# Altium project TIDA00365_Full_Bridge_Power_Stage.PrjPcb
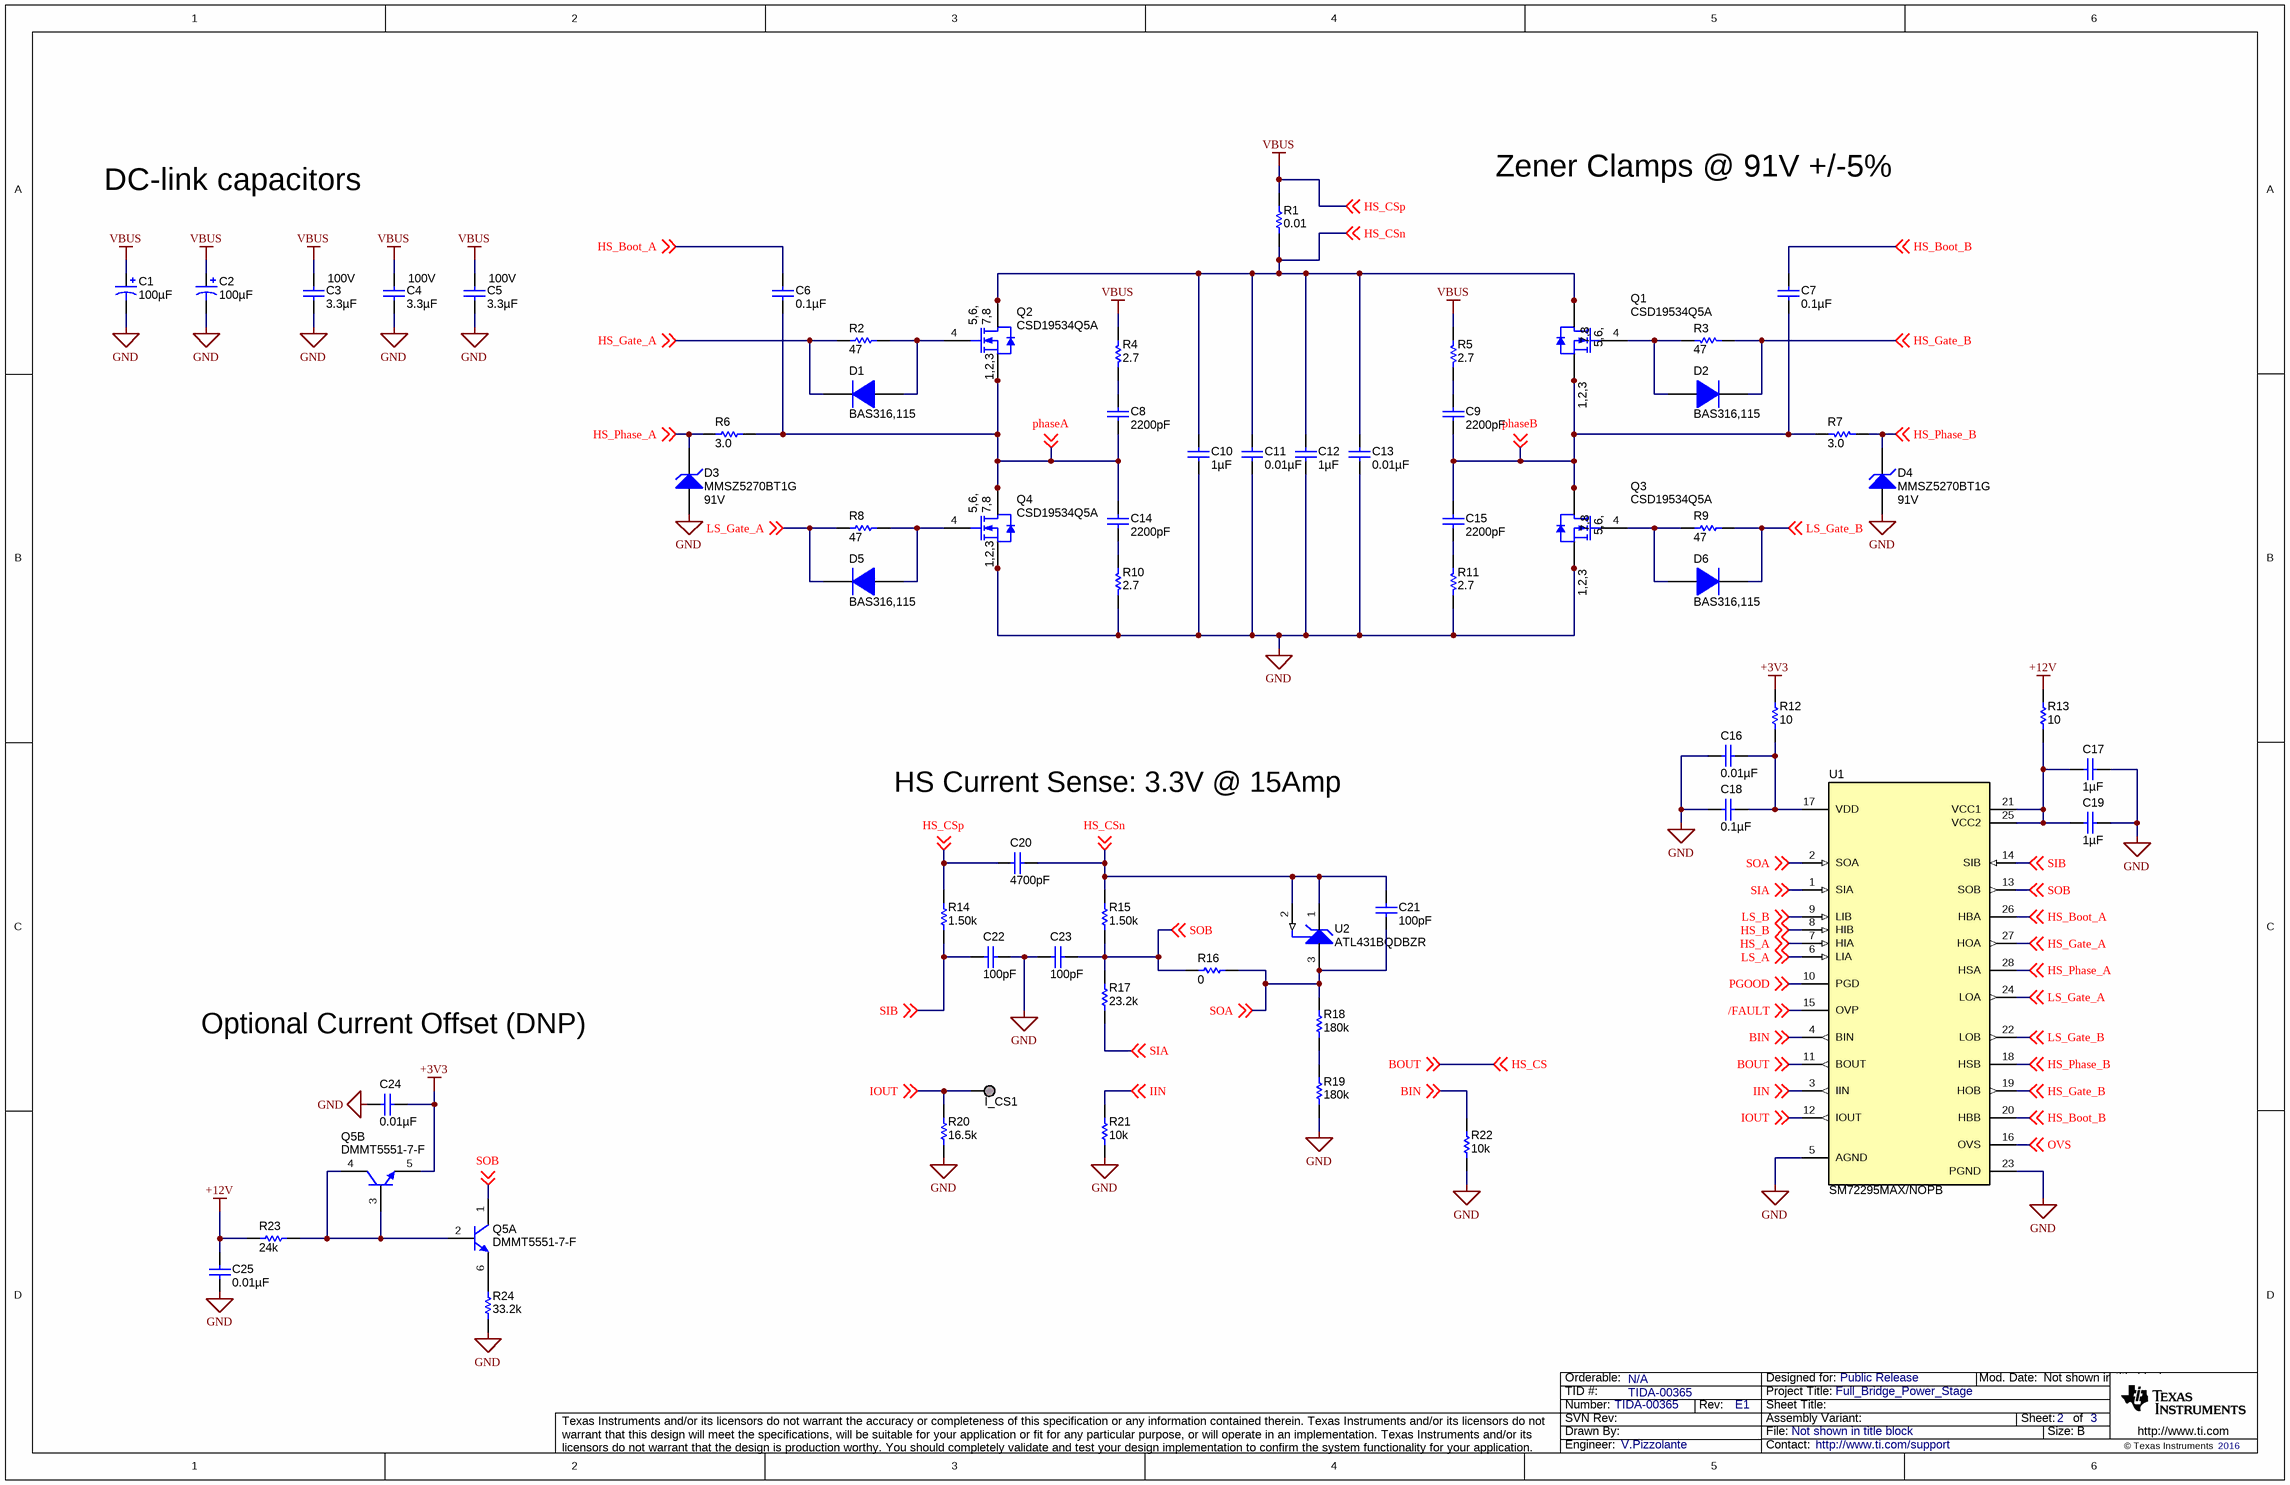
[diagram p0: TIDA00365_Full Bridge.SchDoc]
CopyrightYear: 2016; EVM_Orderable: N/A; PCB_Layout: V.Pizzolante; PCB_Rev: E1; PRJ_Customer: Public Release; PRJ_Engineer: V.Pizzolante; PRJ_Number: TIDA-00365; PRJ_Title: Full_Bridge_Power_Stage; SCH_Rev: E1; TechSupport: http://www.ti.com/support; TID: TIDA-00365
6 sheets, 180 parts. Net scope: global (net labels, ports and power ports of the same name join across sheets).
Board file: TIDA00365.PcbDoc
Sheets:
  TIDA00365_CoverSheet.SchDoc
  TIDA00365_Full Bridge.SchDoc
  TIDA00365_Interfaces.SchDoc
  TIDA00365_Power Supply.SchDoc
  TIDA00365_Protections.SchDoc
  TIDA00365_Hardware.SchDoc

## Sheet TIDA00365_CoverSheet.SchDoc
size 431 x 279 mm; Date: Not shown in title block; ApprovedBy: Not shown in title block; CheckedBy: Not shown in title block; Author: Not shown in title block; CompanyName: Not shown in title block; Engineer: Not shown in title block; Organization: Not shown in title block; Address1: Not shown in title block; Address2: Not shown in title block; Address3: Not shown in title block; Address4: Not shown in title block; DocumentNumber: 1; Revision: Use project parameter SCH_Rev; SheetNumber: 1; SheetTotal: 3

## Sheet TIDA00365_Full Bridge.SchDoc
size 431 x 279 mm; Date: Not shown in title block; ApprovedBy: Not shown in title block; CheckedBy: Not shown in title block; Author: Not shown in title block; CompanyName: Not shown in title block; Engineer: Not shown in title block; Organization: Not shown in title block; Address1: Not shown in title block; Address2: Not shown in title block; Address3: Not shown in title block; Address4: Not shown in title block; DocumentNumber: 1; Revision: Use project parameter SCH_Rev; SheetNumber: 2; SheetTotal: 3

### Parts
C1  ValueDisplayed: 100µF  [WCAP-ATUL_1000x2500]  (hidden comment: 860040875005)
C2  ValueDisplayed: 100µF  [WCAP-ATUL_1000x2500]  (hidden comment: 860040875005)
C3  ValueDisplayed: 3.3µF  Value2: 100V  [1206_190]  (hidden comment: C3216X7S2A335M160AB)
C4  ValueDisplayed: 3.3µF  Value2: 100V  [1206_190]  (hidden comment: C3216X7S2A335M160AB)
C5  ValueDisplayed: 3.3µF  Value2: 100V  [1206_190]  (hidden comment: C3216X7S2A335M160AB)
C6  ValueDisplayed: 0.1µF  [0805_HV]  (hidden comment: C2012X7R2A104K125AA)
C7  ValueDisplayed: 0.1µF  [0805_HV]  (hidden comment: C2012X7R2A104K125AA)
C8  ValueDisplayed: 2200pF  [0603]  (hidden comment: 06031C222JAT2A)
C9  ValueDisplayed: 2200pF  [0603]  (hidden comment: 06031C222JAT2A)
C10  ValueDisplayed: 1µF  [0805_HV]  (hidden comment: C2012X7S2A105K125AB)
C11  ValueDisplayed: 0.01µF  [0603]  (hidden comment: 06031C103KAT2A)
C12  ValueDisplayed: 1µF  [0805_HV]  (hidden comment: C2012X7S2A105K125AB)
C13  ValueDisplayed: 0.01µF  [0603]  (hidden comment: 06031C103KAT2A)
C14  ValueDisplayed: 2200pF  [0603]  (hidden comment: 06031C222JAT2A)
C15  ValueDisplayed: 2200pF  [0603]  (hidden comment: 06031C222JAT2A)
C16  ValueDisplayed: 0.01µF  [0402]  (hidden comment: 885012205031)
C17  ValueDisplayed: 1µF  [0603]  (hidden comment: 885012106017)
C18  ValueDisplayed: 0.1µF  [0402]  (hidden comment: C1005X7R1E104M050BB)
C19  ValueDisplayed: 1µF  [0603]  (hidden comment: 885012106017)
C20  ValueDisplayed: 4700pF  [0402]  (hidden comment: GRM155R72A472KA01D)
C21  ValueDisplayed: 100pF  [0402]  (hidden comment: 885012205055)
C22  ValueDisplayed: 100pF  [0402]  (hidden comment: 885012205055)
C23  ValueDisplayed: 100pF  [0402]  (hidden comment: 885012205055)
C24  ValueDisplayed: 0.01µF  [0402]  (hidden comment: 885012205031)
C25  ValueDisplayed: 0.01µF  [0402]  (hidden comment: 885012205031)
D1  BAS316,115  [sod-323]
D2  BAS316,115  [sod-323]
D3  MMSZ5270BT1G  value 91V  [SOD-123]
D4  MMSZ5270BT1G  value 91V  [SOD-123]
D5  BAS316,115  [sod-323]
D6  BAS316,115  [sod-323]
I_CS1  TESTPOINT  [TP_SM_1MM]  (value not drawn)  (no BOM)
Q1  CSD19534Q5A  [TRANS_NexFET_Q5A]
Q2  CSD19534Q5A  [TRANS_NexFET_Q5A]
Q3  CSD19534Q5A  [TRANS_NexFET_Q5A]
Q4  CSD19534Q5A  [TRANS_NexFET_Q5A]
Q5  DMMT5551-7-F  [SOT-26]  (parts A,B of 2)
R1  ValueDisplayed: 0.01  [2512]  (hidden comment: CRA2512-FZ-R010ELF)
R2  ValueDisplayed: 47  [0603]  (hidden comment: CRCW060347R0JNEA)
R3  ValueDisplayed: 47  [0603]  (hidden comment: CRCW060347R0JNEA)
R4  ValueDisplayed: 2.7  [0805_HV]  (hidden comment: CRCW08052R70JNEA)
R5  ValueDisplayed: 2.7  [0805_HV]  (hidden comment: CRCW08052R70JNEA)
R6  ValueDisplayed: 3.0  [0603]  (hidden comment: CRCW06033R00JNEA)
R7  ValueDisplayed: 3.0  [0603]  (hidden comment: CRCW06033R00JNEA)
R8  ValueDisplayed: 47  [0603]  (hidden comment: CRCW060347R0JNEA)
R9  ValueDisplayed: 47  [0603]  (hidden comment: CRCW060347R0JNEA)
R10  ValueDisplayed: 2.7  [0805_HV]  (hidden comment: CRCW08052R70JNEA)
R11  ValueDisplayed: 2.7  [0805_HV]  (hidden comment: CRCW08052R70JNEA)
R12  ValueDisplayed: 10  [0603]  (hidden comment: CRCW060310R0JNEA)
R13  ValueDisplayed: 10  [0603]  (hidden comment: CRCW060310R0JNEA)
R14  ValueDisplayed: 1.50k  [0402]  (hidden comment: CRCW04021K50FKED)
R15  ValueDisplayed: 1.50k  [0402]  (hidden comment: CRCW04021K50FKED)
R16  ValueDisplayed: 0  [0402]  (hidden comment: CRCW04020000Z0ED)
R17  ValueDisplayed: 23.2k  [0402]  (hidden comment: CRCW040223K2FKED)
R18  ValueDisplayed: 180k  [0402]  (hidden comment: CRCW0402180KJNED)
R19  ValueDisplayed: 180k  [0402]  (hidden comment: CRCW0402180KJNED)
R20  ValueDisplayed: 16.5k  [0402]  (hidden comment: CRCW040216K5FKED)
R21  ValueDisplayed: 10k  [0402]  (hidden comment: CRCW040210K0JNED)
R22  ValueDisplayed: 10k  [0402]  (hidden comment: CRCW040210K0JNED)
R23  ValueDisplayed: 24k  [0402]  (hidden comment: CRCW040224K0JNED)
R24  ValueDisplayed: 33.2k  [0402]  (hidden comment: CRCW040233K2FKED)
U1  SM72295MAX/NOPB  [DW0028A_N]
U2  ATL431BQDBZR  [DBZ0003A_N]

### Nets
+3V3: C24.1 Q5.5(E) R12.2
+12V: C25.1 R13.2 R23.2
GND: C1.2(-) C2.2(-) C3.2 C4.2 C5.2 C10.2 C11.2 C12.2 C13.2 C16.2 C17.1 C18.2 C19.1 C22.1 C23.2 C24.2 C25.2 D3.2(A) D4.2(A) Q3.1(S) Q3.2(S) Q3.3(S) Q4.1(S) Q4.2(S) Q4.3(S) R10.2 R11.2 R19.1 R20.1 R21.1 R22.1 R24.1 U1.5(AGND) U1.23(PGND)
VBUS: C1.1(+) C2.1(+) C3.1 C4.1 C5.1 C20.1 R1.2 R4.2 R5.2 R14.2 ; off-sheet HS_CSp  [also labelled HS_CSp]
/FAULT: U1.15(OVP) ; off-sheet /FAULT
BIN: R22.2 U1.4(BIN) ; off-sheet BIN
BOUT: U1.11(BOUT) ; off-sheet BOUT, off-sheet HS_CS  [also labelled HS_CS]
HS_A: U1.7(HIA) ; off-sheet HS_A
HS_B: U1.8(HIB) ; off-sheet HS_B
HS_Boot_A: C6.1 U1.26(HBA) ; off-sheet HS_Boot_A
HS_Boot_B: C7.1 U1.20(HBB) ; off-sheet HS_Boot_B
HS_CSn: C10.1 C11.1 C12.1 C13.1 C20.2 C21.1 Q1.5(D) Q1.6(D) Q1.7(D) Q1.8(D) Q1.9(D) Q2.5(D) Q2.6(D) Q2.7(D) Q2.8(D) Q2.9(D) R1.1 R15.2 U2.1(CATHODE) U2.2(REF) ; off-sheet HS_CSn
HS_Gate_A: D1.1(K) R2.1 U1.27(HOA) ; off-sheet HS_Gate_A
HS_Gate_B: D2.1(K) R3.1 U1.19(HOB) ; off-sheet HS_Gate_B
HS_Phase_A: D3.1(K) R6.1 U1.28(HSA) ; off-sheet HS_Phase_A
HS_Phase_B: D4.1(K) R7.1 U1.18(HSB) ; off-sheet HS_Phase_B
IIN: R21.2 U1.3(IIN) ; off-sheet IIN
IOUT: I_CS1.1 R20.2 U1.12(IOUT) ; off-sheet IOUT
LS_A: U1.6(LIA) ; off-sheet LS_A
LS_B: U1.9(LIB) ; off-sheet LS_B
LS_Gate_A: D5.1(K) R8.1 U1.24(LOA) ; off-sheet LS_Gate_A
LS_Gate_B: D6.1(K) R9.2 U1.22(LOB) ; off-sheet LS_Gate_B
OVS: U1.16(OVS) ; off-sheet OVS
PGOOD: U1.10(PGD) ; off-sheet PGOOD
phaseA: C6.2 C8.2 C14.2 Q2.1(S) Q2.2(S) Q2.3(S) Q4.5(D) Q4.6(D) Q4.7(D) Q4.8(D) Q4.9(D) R6.2 ; off-sheet phaseA
phaseB: C7.2 C9.2 C15.2 Q1.1(S) Q1.2(S) Q1.3(S) Q3.5(D) Q3.6(D) Q3.7(D) Q3.8(D) Q3.9(D) R7.2 ; off-sheet phaseB
SIA: R17.1 U1.1(SIA) ; off-sheet SIA
SIB: C22.2 R14.1 U1.14(SIB) ; off-sheet SIB
SOA: C21.2 R16.1 R18.1 U1.2(SOA) U2.3(ANODE) ; off-sheet SOA
SOB: C23.1 Q5.1(C) R15.1 R16.2 R17.2 U1.13(SOB) ; off-sheet SOB
NetC8_1: C8.1 R4.1
NetC9_1: C9.1 R5.1
NetC14_1: C14.1 R10.1
NetC15_1: C15.1 R11.1
NetC16_1: C16.1 C18.1 R12.1 U1.17(VDD)
NetC17_2: C17.2 C19.2 R13.1 U1.21(VCC1) U1.25(VCC2)
NetD1_2: D1.2(A) Q2.4(G) R2.2
NetD2_2: D2.2(A) Q1.4(G) R3.2
NetD5_2: D5.2(A) Q4.4(G) R8.2
NetD6_2: D6.2(A) Q3.4(G) R9.1
NetQ5_2: Q5.2(B) Q5.3(B) Q5.4(C) R23.1
NetQ5_6: Q5.6(E) R24.2
NetR18_2: R18.2 R19.2

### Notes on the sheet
- Zener Clamps @ 91V +/-5%
- DC-link capacitors
- HS Current Sense: 3.3V @ 15Amp
- Optional Current Offset (DNP)

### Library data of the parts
C1 C2 = 860040875005: CAP, AL, 100 µF, 100 V, +/- 20%, 0.2 ohm, TH; Manufacturer: Wurth Elektronik; Polarized: Y; CompType: Capacitor; Value: 100uF; U/M: EA; Cap_F: 0.0001; Tolerance_%: 20; Value1: 0.2 ohm; VDC_V: 100; Value2: 100V; ESR_ohm: 0.2; IRMS_A: 0.8; TaMin_C: -40; TaMax_C: 105; Cap_Case: 10x25mm; AEC Category: Q200; AEC Qualified: N
C3-C5 = C3216X7S2A335M160AB: CAP, CERM, 3.3 µF, 100 V, +/- 20%, X7S, 1206_190; Manufacturer: TDK; Polarized: N; CompType: Capacitor; Value: 3.3uF; U/M: EA; Cap_F: 0.0000033; Tolerance_%: 20; Value1: Unknown; VDC_V: 100; TaMin_C: -55; TaMax_C: 125; Cap_Case: 1206; AEC Category: Q200
C6 C7 = C2012X7R2A104K125AA: CAP, CERM, 0.1 µF, 100 V, +/- 10%, X7R, 0805; Manufacturer: TDK; Polarized: N; CompType: Capacitor; Value: 0.1uF; U/M: EA; Cap_F: 0.0000001; Tolerance_%: 10; ESR_ohm: 0.0158; Value1: 0.0158 ohm; VDC_V: 100; Value2: 100V; TaMin_C: -55; TaMax_C: 125; Cap_Case: 0805; AEC Category: Q200
C8 C9 C14 C15 = 06031C222JAT2A: CAP, CERM, 2200 pF, 100 V, +/- 5%, X7R, 0603; Manufacturer: AVX; Polarized: N; CompType: Capacitor; Value: 2200pF; U/M: EA; Cap_F: 0.0000000022; Tolerance_%: 5; ESR_ohm: 0.192; Value1: 0.192 ohm; VDC_V: 100; Value2: 100V; TaMin_C: -55; TaMax_C: 125; AEC Category: Q200
C10 C12 = C2012X7S2A105K125AB: CAP, CERM, 1 µF, 100 V, +/- 10%, X7S, 0805; Manufacturer: TDK; Polarized: N; CompType: Capacitor; Value: 1uF; U/M: EA; Cap_F: 0.000001; Tolerance_%: 10; Value1: Unknown; VDC_V: 100; Value2: 100V; TaMin_C: -55; TaMax_C: 125; Cap_Case: 0805; AEC Category: Q200
C11 C13 = 06031C103KAT2A: CAP, CERM, 0.01 µF, 100 V, +/- 10%, X7R, 0603; Manufacturer: AVX; Polarized: N; CompType: Capacitor; Value: 0.01uF; U/M: EA; Cap_F: 0.00000001; Tolerance_%: 10; ESR_ohm: 0.098; Value1: 0.098 ohm; VDC_V: 100; Value2: 100V; TaMin_C: -55; TaMax_C: 125; AEC Category: Q200
C16 C24 C25 = 885012205031: CAP, CERM, 0.01 µF, 16 V, +/- 10%, X7R, 0402; Manufacturer: Wurth Elektronik; Polarized: N; CompType: Capacitor; Value: 0.01uF; U/M: EA; Cap_F: 0.00000001; Tolerance_%: 10; Value1: Unknown; VDC_V: 16; Value2: 16V; TaMin_C: -55; TaMax_C: 125; AEC Category: Q200
C17 C19 = 885012106017: CAP, CERM, 1 µF, 16 V, +/- 20%, X5R, 0603; Manufacturer: Wurth Elektronik; Polarized: N; CompType: Capacitor; Value: 1uF; U/M: EA; Cap_F: 0.000001; Tolerance_%: 20; Value1: Unknown; VDC_V: 16; Value2: 16V; TaMin_C: -55; TaMax_C: 85; AEC Category: Q200
C18 = C1005X7R1E104M050BB: CAP, CERM, 0.1 µF, 25 V, +/- 20%, X7R, 0402; Manufacturer: TDK; Polarized: N; CompType: Capacitor; Value: 0.1uF; U/M: EA; Cap_F: 0.0000001; Tolerance_%: 20; Value1: Unknown; VDC_V: 25; Value2: 25V; TaMin_C: -55; TaMax_C: 125; AEC Category: Q200
C20 = GRM155R72A472KA01D: CAP, CERM, 4700 pF, 100 V, +/- 10%, X7R, 0402; Manufacturer: MuRata; Polarized: N; CompType: Capacitor; Value: 4700pF; U/M: EA; Cap_F: 0.0000000047; Tolerance_%: 10; Value1: Unknown; VDC_V: 100; Value2: 100V; TaMin_C: -55; TaMax_C: 125; AEC Category: Q200
C21-C23 = 885012205055: CAP, CERM, 100 pF, 50 V, +/- 10%, X7R, 0402; Manufacturer: Wurth Elektronik; Polarized: N; CompType: Capacitor; Value: 100pF; U/M: EA; Cap_F: 0.0000000001; Tolerance_%: 10; Value1: Unknown; VDC_V: 50; Value2: 50V; TaMin_C: -55; TaMax_C: 125; AEC Category: Q200
D1 D2 D5 D6 = BAS316,115: Diode, Ultrafast, 100 V, 0.25 A, SOD-323; Manufacturer: NXP Semiconductor; U/M: EA; Vf_V: 1.4; Value: 100V; Value1: 0.25A; Value2: 1.4V; Io_A: 0.25; Vr_V: 100; TJmax_C: 150; AEC Category: Q101
D3 D4 = MMSZ5270BT1G: Diode, Zener, 91 V, 500 mW, SOD-123; Manufacturer: ON Semiconductor; SymbolCreator: a0412235; U/M: EA; Power_W: 0.5; Vz_V: 91; Value1: 0.5W; RJA_CperW: 340; AEC Category: Q101
I_CS1 = TP_SM_1MM: 1mm Test Point, SMT; Manufacturer: Any
Q1-Q4 = CSD19534Q5A: MOSFET, N-CH, 100 V, 10 A, SON 5x6mm; Manufacturer: Texas Instruments; Alternate Manufacturer: None; U/M: EA; ChType: N; Value: 100V; VdsMax_V: 100; Value1: ? ohm; Value2: 17 nC; QgTyp_nC: 17; Vgs_V: 20; IdsMax_A: 10; AEC Category: Q101
Q5 = DMMT5551-7-F, Diodes Inc.: Transistor, Dual NPN, 160 V, 0.2 A, SOT-26; SymbolCreator: Altium; PNP: 0; NPN: 2; Vceo_V: 160; Vcesat1_V: 0.15; Value: 160 V; IcRated_A: 0.2; Value1: 0.2 A; HfeMax: 250; TaMin_C: -55; TaMax_C: 150; CompType: BJT; U/M: EA; AEC Category: Q101; AEC Qualified: N
R1 = CRA2512-FZ-R010ELF: RES, 0.01, 1%, 3 W, 2512; Manufacturer: Bourns; CompType: Resistor; Value: 0.01; Value_Code: R010; Tolerance_%: 1; Power_W: 3; Value2: 3W; TempCo: 75 ppm/C; EIA_Code: E96; U/M: EA; AEC Category: Q200
R2 R3 R8 R9 = CRCW060347R0JNEA: RES, 47, 5%, 0.1 W, 0603; Manufacturer: Vishay-Dale; CompType: Resistor; Value: 47; Value_Code: 47R0; Tolerance_%: 5; Power_W: 0.1; Value2: 0.1W; VDC_V: 75; TempCo: 200 ppm/C; EIA_Code: E24; U/M: EA; AEC Category: Q200
R4 R5 R10 R11 = CRCW08052R70JNEA: RES, 2.7, 5%, 0.125 W, 0805; Manufacturer: Vishay-Dale; CompType: Resistor; Value: 2.7; Value_Code: 2R70; Tolerance_%: 5; Power_W: 0.125; Value2: 0.125W; VDC_V: 150; TempCo: 200 ppm/C; EIA_Code: E24; U/M: EA; AEC Category: Q200
R6 R7 = CRCW06033R00JNEA: RES, 3.0, 5%, 0.1 W, 0603; Manufacturer: Vishay-Dale; CompType: Resistor; Value: 3.0; Res_ohm: 3; Value_Code: 3R00; Tolerance_%: 5; Power_W: 0.1; Value2: 0.1W; VDC_V: 75; TempCo: 200 ppm/C; EIA_Code: E24; U/M: EA; AEC Category: Q200
R12 R13 = CRCW060310R0JNEA: RES, 10, 5%, 0.1 W, 0603; Manufacturer: Vishay-Dale; CompType: Resistor; Value: 10; Value_Code: 10R0; Tolerance_%: 5; Power_W: 0.1; Value2: 0.1W; VDC_V: 75; TempCo: 200 ppm/C; EIA_Code: E24; U/M: EA; AEC Category: Q200
R14 R15 = CRCW04021K50FKED: RES, 1.50 k, 1%, 0.063 W, 0402; Manufacturer: Vishay-Dale; CompType: Resistor; Value: 1.50k; Res_ohm: 1500; Value_Code: 1k50; Tolerance_%: 1; Power_W: 0.063; Value2: 0.063W; VDC_V: 50; TempCo: 100 ppm/C; EIA_Code: E96; U/M: EA; AEC Category: Q200
R16 = CRCW04020000Z0ED: RES, 0, 5%, 0.063 W, 0402; Manufacturer: Vishay-Dale; CompType: Resistor; Value: 0; Value_Code: 0000; Tolerance_%: 5; Power_W: 0.063; Value2: 0.063W; VDC_V: 50; TempCo: 200 ppm/C; EIA_Code: E24; U/M: EA; AEC Category: Q200
R17 = CRCW040223K2FKED: RES, 23.2 k, 1%, 0.063 W, 0402; Manufacturer: Vishay-Dale; CompType: Resistor; Value: 23.2k; Res_ohm: 23200; Value_Code: 23k2; Tolerance_%: 1; Power_W: 0.063; Value2: 0.063W; VDC_V: 50; TempCo: 100 ppm/C; EIA_Code: E96; U/M: EA; AEC Category: Q200
R18 R19 = CRCW0402180KJNED: RES, 180 k, 5%, 0.063 W, 0402; Manufacturer: Vishay-Dale; CompType: Resistor; Value: 180k; Res_ohm: 180000; Tolerance_%: 5; Power_W: 0.063; Value2: 0.063W; VDC_V: 50; TempCo: 200 ppm/C; EIA_Code: E24; U/M: EA; AEC Category: Q200
R20 = CRCW040216K5FKED: RES, 16.5 k, 1%, 0.063 W, 0402; Manufacturer: Vishay-Dale; CompType: Resistor; Value: 16.5k; Res_ohm: 16500; Value_Code: 16k5; Tolerance_%: 1; Power_W: 0.063; Value2: 0.063W; VDC_V: 50; TempCo: 100 ppm/C; EIA_Code: E96; U/M: EA; AEC Category: Q200
R21 R22 = CRCW040210K0JNED: RES, 10 k, 5%, 0.063 W, 0402; Manufacturer: Vishay-Dale; CompType: Resistor; Value: 10k; Res_ohm: 10000; Value_Code: 10k0; Tolerance_%: 5; Power_W: 0.063; Value2: 0.063W; VDC_V: 50; TempCo: 200 ppm/C; EIA_Code: E24; U/M: EA; AEC Category: Q200
R23 = CRCW040224K0JNED: RES, 24 k, 5%, 0.063 W, 0402; Manufacturer: Vishay-Dale; CompType: Resistor; Value: 24k; Res_ohm: 24000; Value_Code: 24k0; Tolerance_%: 5; Power_W: 0.063; Value2: 0.063W; VDC_V: 50; TempCo: 200 ppm/C; EIA_Code: E24; U/M: EA; AEC Category: Q200
R24 = CRCW040233K2FKED: RES, 33.2 k, 1%, 0.063 W, 0402; Manufacturer: Vishay-Dale; CompType: Resistor; Value: 33.2k; Res_ohm: 33200; Value_Code: 33k2; Tolerance_%: 1; Power_W: 0.063; Value2: 0.063W; VDC_V: 50; TempCo: 100 ppm/C; EIA_Code: E96; U/M: EA; AEC Category: Q200
U1 = SM72295MAX/NOPB: Photovoltaic Full Bridge Driver, DW0028A; Alternate PartNumber: SM72295MAE/NOPB; Manufacturer: Texas Instruments; SymbolCreator: a0411947; CompType: IC; U/M: EA
U2 = ATL431BQDBZR: 2.5V Low Iq Adjustable Precision Shunt Regulator, DBZ0003A; Alternate PartNumber: ATL431BQDBZT; Manufacturer: Texas Instruments; SymbolCreator: a0412235; CompType: IC; U/M: EA

## Sheet TIDA00365_Interfaces.SchDoc
size 431 x 279 mm; Date: Not shown in title block; ApprovedBy: Not shown in title block; CheckedBy: Not shown in title block; Author: Not shown in title block; CompanyName: Not shown in title block; Engineer: Not shown in title block; Organization: Not shown in title block; Address1: Not shown in title block; Address2: Not shown in title block; Address3: Not shown in title block; Address4: Not shown in title block; DocumentNumber: 1; Revision: Use project parameter SCH_Rev; SheetNumber: 2; SheetTotal: 3
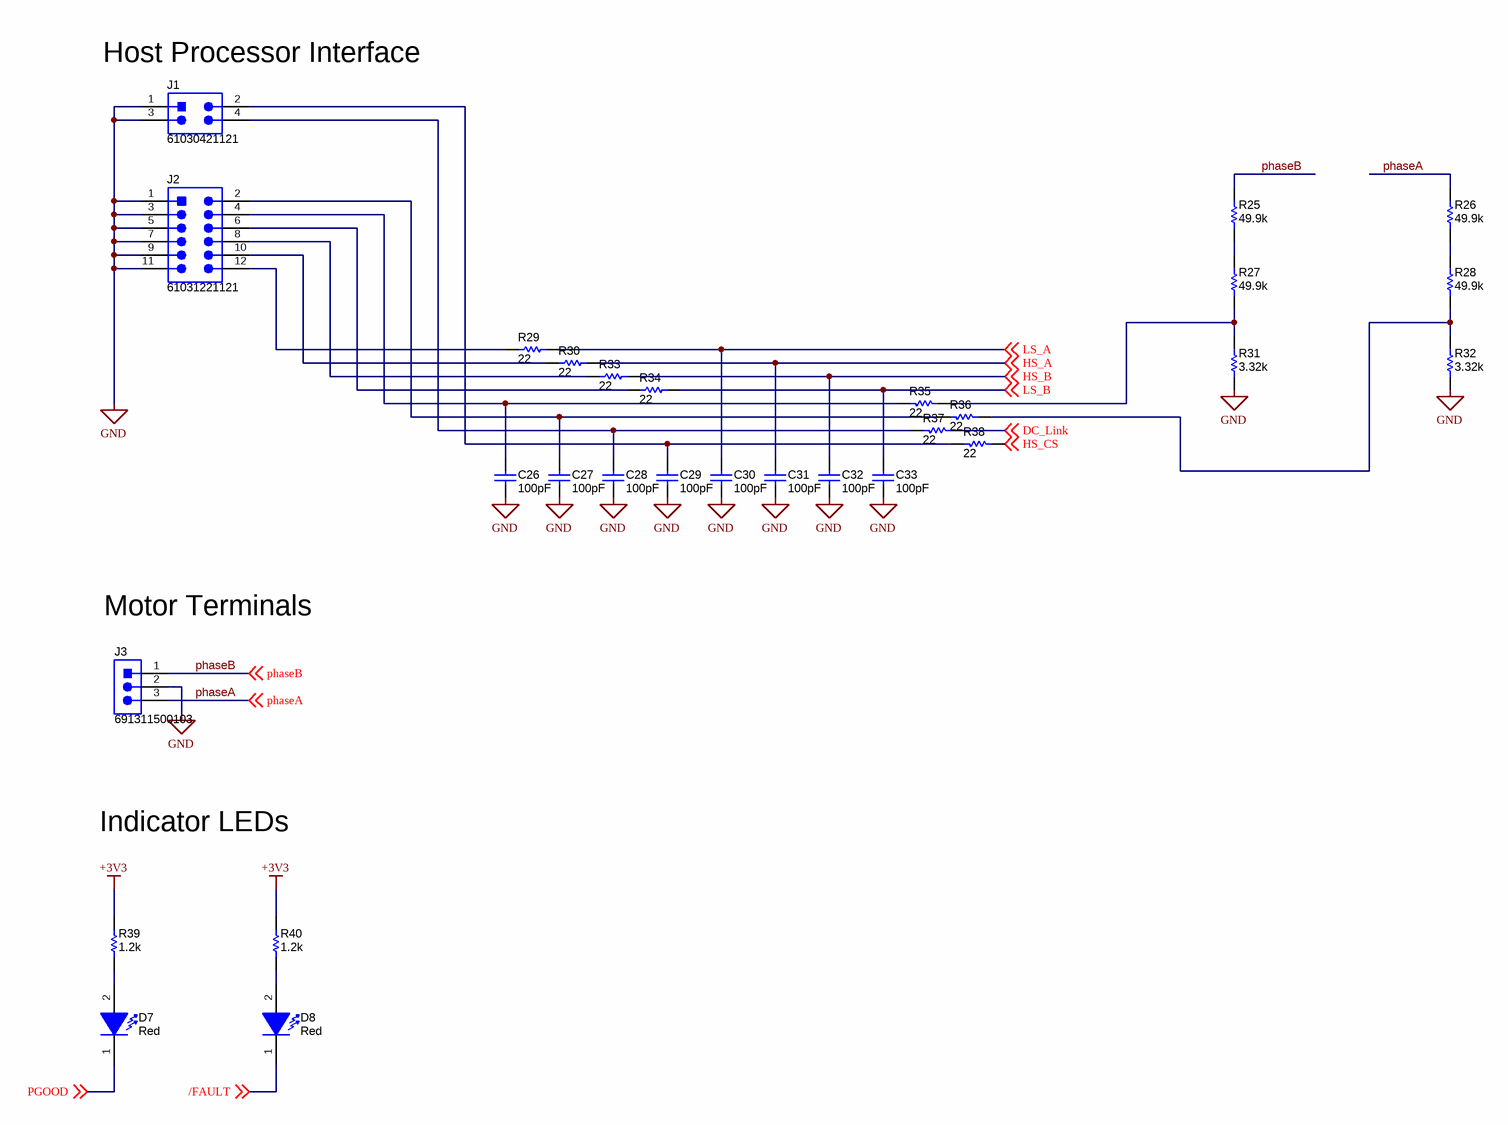
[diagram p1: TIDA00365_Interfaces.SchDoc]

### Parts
C26  ValueDisplayed: 100pF  [0402]  (hidden comment: CC0402KRX7R9BB101)
C27  ValueDisplayed: 100pF  [0402]  (hidden comment: CC0402KRX7R9BB101)
C28  ValueDisplayed: 100pF  [0402]  (hidden comment: CC0402KRX7R9BB101)
C29  ValueDisplayed: 100pF  [0402]  (hidden comment: CC0402KRX7R9BB101)
C30  ValueDisplayed: 100pF  [0402]  (hidden comment: CC0402KRX7R9BB101)
C31  ValueDisplayed: 100pF  [0402]  (hidden comment: CC0402KRX7R9BB101)
C32  ValueDisplayed: 100pF  [0402]  (hidden comment: CC0402KRX7R9BB101)
C33  ValueDisplayed: 100pF  [0402]  (hidden comment: CC0402KRX7R9BB101)
D7  value Red  [WL-SMCW_RED]  (hidden comment: 150060RS75000)
D8  value Red  [WL-SMCW_RED]  (hidden comment: 150060RS75000)
J1  61030421121  [Wurth_61030421121]
J2  61031221121  [Wurth_61031221121]
J3  691311500103  [Wurth_691311500103]
R25  ValueDisplayed: 49.9k  [0402]  (hidden comment: CRCW040249K9FKED)
R26  ValueDisplayed: 49.9k  [0402]  (hidden comment: CRCW040249K9FKED)
R27  ValueDisplayed: 49.9k  [0402]  (hidden comment: CRCW040249K9FKED)
R28  ValueDisplayed: 49.9k  [0402]  (hidden comment: CRCW040249K9FKED)
R29  ValueDisplayed: 22  [0402]  (hidden comment: CRCW040222R0JNED)
R30  ValueDisplayed: 22  [0402]  (hidden comment: CRCW040222R0JNED)
R31  ValueDisplayed: 3.32k  [0402]  (hidden comment: CRCW04023K32FKED)
R32  ValueDisplayed: 3.32k  [0402]  (hidden comment: CRCW04023K32FKED)
R33  ValueDisplayed: 22  [0402]  (hidden comment: CRCW040222R0JNED)
R34  ValueDisplayed: 22  [0402]  (hidden comment: CRCW040222R0JNED)
R35  ValueDisplayed: 22  [0402]  (hidden comment: CRCW040222R0JNED)
R36  ValueDisplayed: 22  [0402]  (hidden comment: CRCW040222R0JNED)
R37  ValueDisplayed: 22  [0402]  (hidden comment: CRCW040222R0JNED)
R38  ValueDisplayed: 22  [0402]  (hidden comment: CRCW040222R0JNED)
R39  ValueDisplayed: 1.2k  [0402]  (hidden comment: CRCW04021K20JNED)
R40  ValueDisplayed: 1.2k  [0402]  (hidden comment: CRCW04021K20JNED)

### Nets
+3V3: R39.2 R40.2
GND: C26.1 C27.1 C28.1 C29.1 C30.2 C31.2 C32.2 C33.2 J1.1 J1.3 J2.1 J2.3 J2.5 J2.7 J2.9 J2.11 J3.2 R31.1 R32.1
/FAULT: D8.1(K) ; off-sheet /FAULT
DC_Link: R37.2 ; off-sheet DC_Link
HS_A: C31.1 R30.2 ; off-sheet HS_A
HS_B: C32.1 R33.2 ; off-sheet HS_B
HS_CS: R38.2 ; off-sheet HS_CS  [project net BOUT]
LS_A: C30.1 R29.2 ; off-sheet LS_A
LS_B: C33.1 R34.2 ; off-sheet LS_B
PGOOD: D7.1(K) ; off-sheet PGOOD
phaseA: J3.3 R26.2 ; off-sheet phaseA
phaseB: J3.1 R25.2 ; off-sheet phaseB
NetC26_2: C26.2 J2.4 R35.1
NetC27_2: C27.2 J2.2 R36.1
NetC28_2: C28.2 J1.4 R37.1
NetC29_2: C29.2 J1.2 R38.1
NetD7_2: D7.2(A) R39.1
NetD8_2: D8.2(A) R40.1
NetJ2_6: J2.6 R34.1
NetJ2_8: J2.8 R33.1
NetJ2_10: J2.10 R30.1
NetJ2_12: J2.12 R29.1
NetR25_1: R25.1 R27.2
NetR26_1: R26.1 R28.2
NetR27_1: R27.1 R31.2 R35.2
NetR28_1: R28.1 R32.2 R36.2

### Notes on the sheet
- (near J1) Host Processor Interface
- (near J3) Motor Terminals
- Indicator LEDs

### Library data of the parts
C26-C33 = CC0402KRX7R9BB101: CAP, CERM, 100 pF, 50 V, +/- 10%, X7R, 0402; Manufacturer: Yageo America; Polarized: N; CompType: Capacitor; Value: 100pF; U/M: EA; Cap_F: 0.0000000001; Tolerance_%: 10; Value1: Unknown; VDC_V: 50; Value2: 50V; TaMin_C: -55; TaMax_C: 125; AEC Category: Q200
D7 D8 = 150060RS75000: LED, Red, SMD; Manufacturer: Wurth Elektronik; Type: AlInGaP; Vf_V: 2; Value2: 2V; Io_A: 0.03; Vr_V: 5; Tjmax_C: 85; Power_TotalModule: 0.072; Value1: 0.072W; Angle: 140; U/M: EA
J1 = 61030421121: Header, 2.54mm, 2x2, Gold, SMT; Manufacturer: Wurth Elektronik; SymbolCreator: a0412235; Pitch_mm: 2.54; Gender: Male; Shrouded: N; Row_Count: 2; Current_A: 3; Voltage_V: 250
J2 = 61031221121: Header, 2.54mm, 6x2, Gold, SMT; Manufacturer: Wurth Elektronik; SymbolCreator: a0412235; Pitch_mm: 2.54; Gender: Male; Shrouded: N; Row_Count: 2; Current_A: 3; Voltage_V: 250
J3 = 691311500103: Header (Shrouded), 5.08mm, 3x1, Tin, TH; Manufacturer: Wurth Elektronik; SymbolCreator: a0799628; Pitch_mm: 5.08; Gender: Male; Shrouded: Y; Row_Count: 1; Current_A: 20; Voltage_V: 300
R25-R28 = CRCW040249K9FKED: RES, 49.9 k, 1%, 0.063 W, 0402; Manufacturer: Vishay-Dale; CompType: Resistor; Value: 49.9k; Res_ohm: 49900; Value_Code: 49k9; Tolerance_%: 1; Power_W: 0.063; Value2: 0.063W; VDC_V: 50; TempCo: 100 ppm/C; EIA_Code: E96; U/M: EA; AEC Category: Q200
R29 R30 R33-R38 = CRCW040222R0JNED: RES, 22, 5%, 0.063 W, 0402; Manufacturer: Vishay-Dale; CompType: Resistor; Value: 22; Value_Code: 22R0; Tolerance_%: 5; Power_W: 0.063; Value2: 0.063W; VDC_V: 50; TempCo: 200 ppm/C; EIA_Code: E24; U/M: EA; AEC Category: Q200
R31 R32 = CRCW04023K32FKED: RES, 3.32 k, 1%, 0.063 W, 0402; Manufacturer: Vishay-Dale; CompType: Resistor; Value: 3.32k; Res_ohm: 3320; Value_Code: 3k32; Tolerance_%: 1; Power_W: 0.063; Value2: 0.063W; VDC_V: 50; TempCo: 100 ppm/C; EIA_Code: E96; U/M: EA; AEC Category: Q200
R39 R40 = CRCW04021K20JNED: RES, 1.2 k, 5%, 0.063 W, 0402; Manufacturer: Vishay-Dale; CompType: Resistor; Value: 1.2k; Res_ohm: 1200; Value_Code: 1k20; Tolerance_%: 5; Power_W: 0.063; Value2: 0.063W; VDC_V: 50; TempCo: 200 ppm/C; EIA_Code: E24; U/M: EA; AEC Category: Q200

## Sheet TIDA00365_Power Supply.SchDoc
size 431 x 279 mm; Date: Not shown in title block; ApprovedBy: Not shown in title block; CheckedBy: Not shown in title block; Author: Not shown in title block; CompanyName: Not shown in title block; Engineer: Not shown in title block; Organization: Not shown in title block; Address1: Not shown in title block; Address2: Not shown in title block; Address3: Not shown in title block; Address4: Not shown in title block; DocumentNumber: 1; Revision: Use project parameter SCH_Rev; SheetNumber: 2; SheetTotal: 3
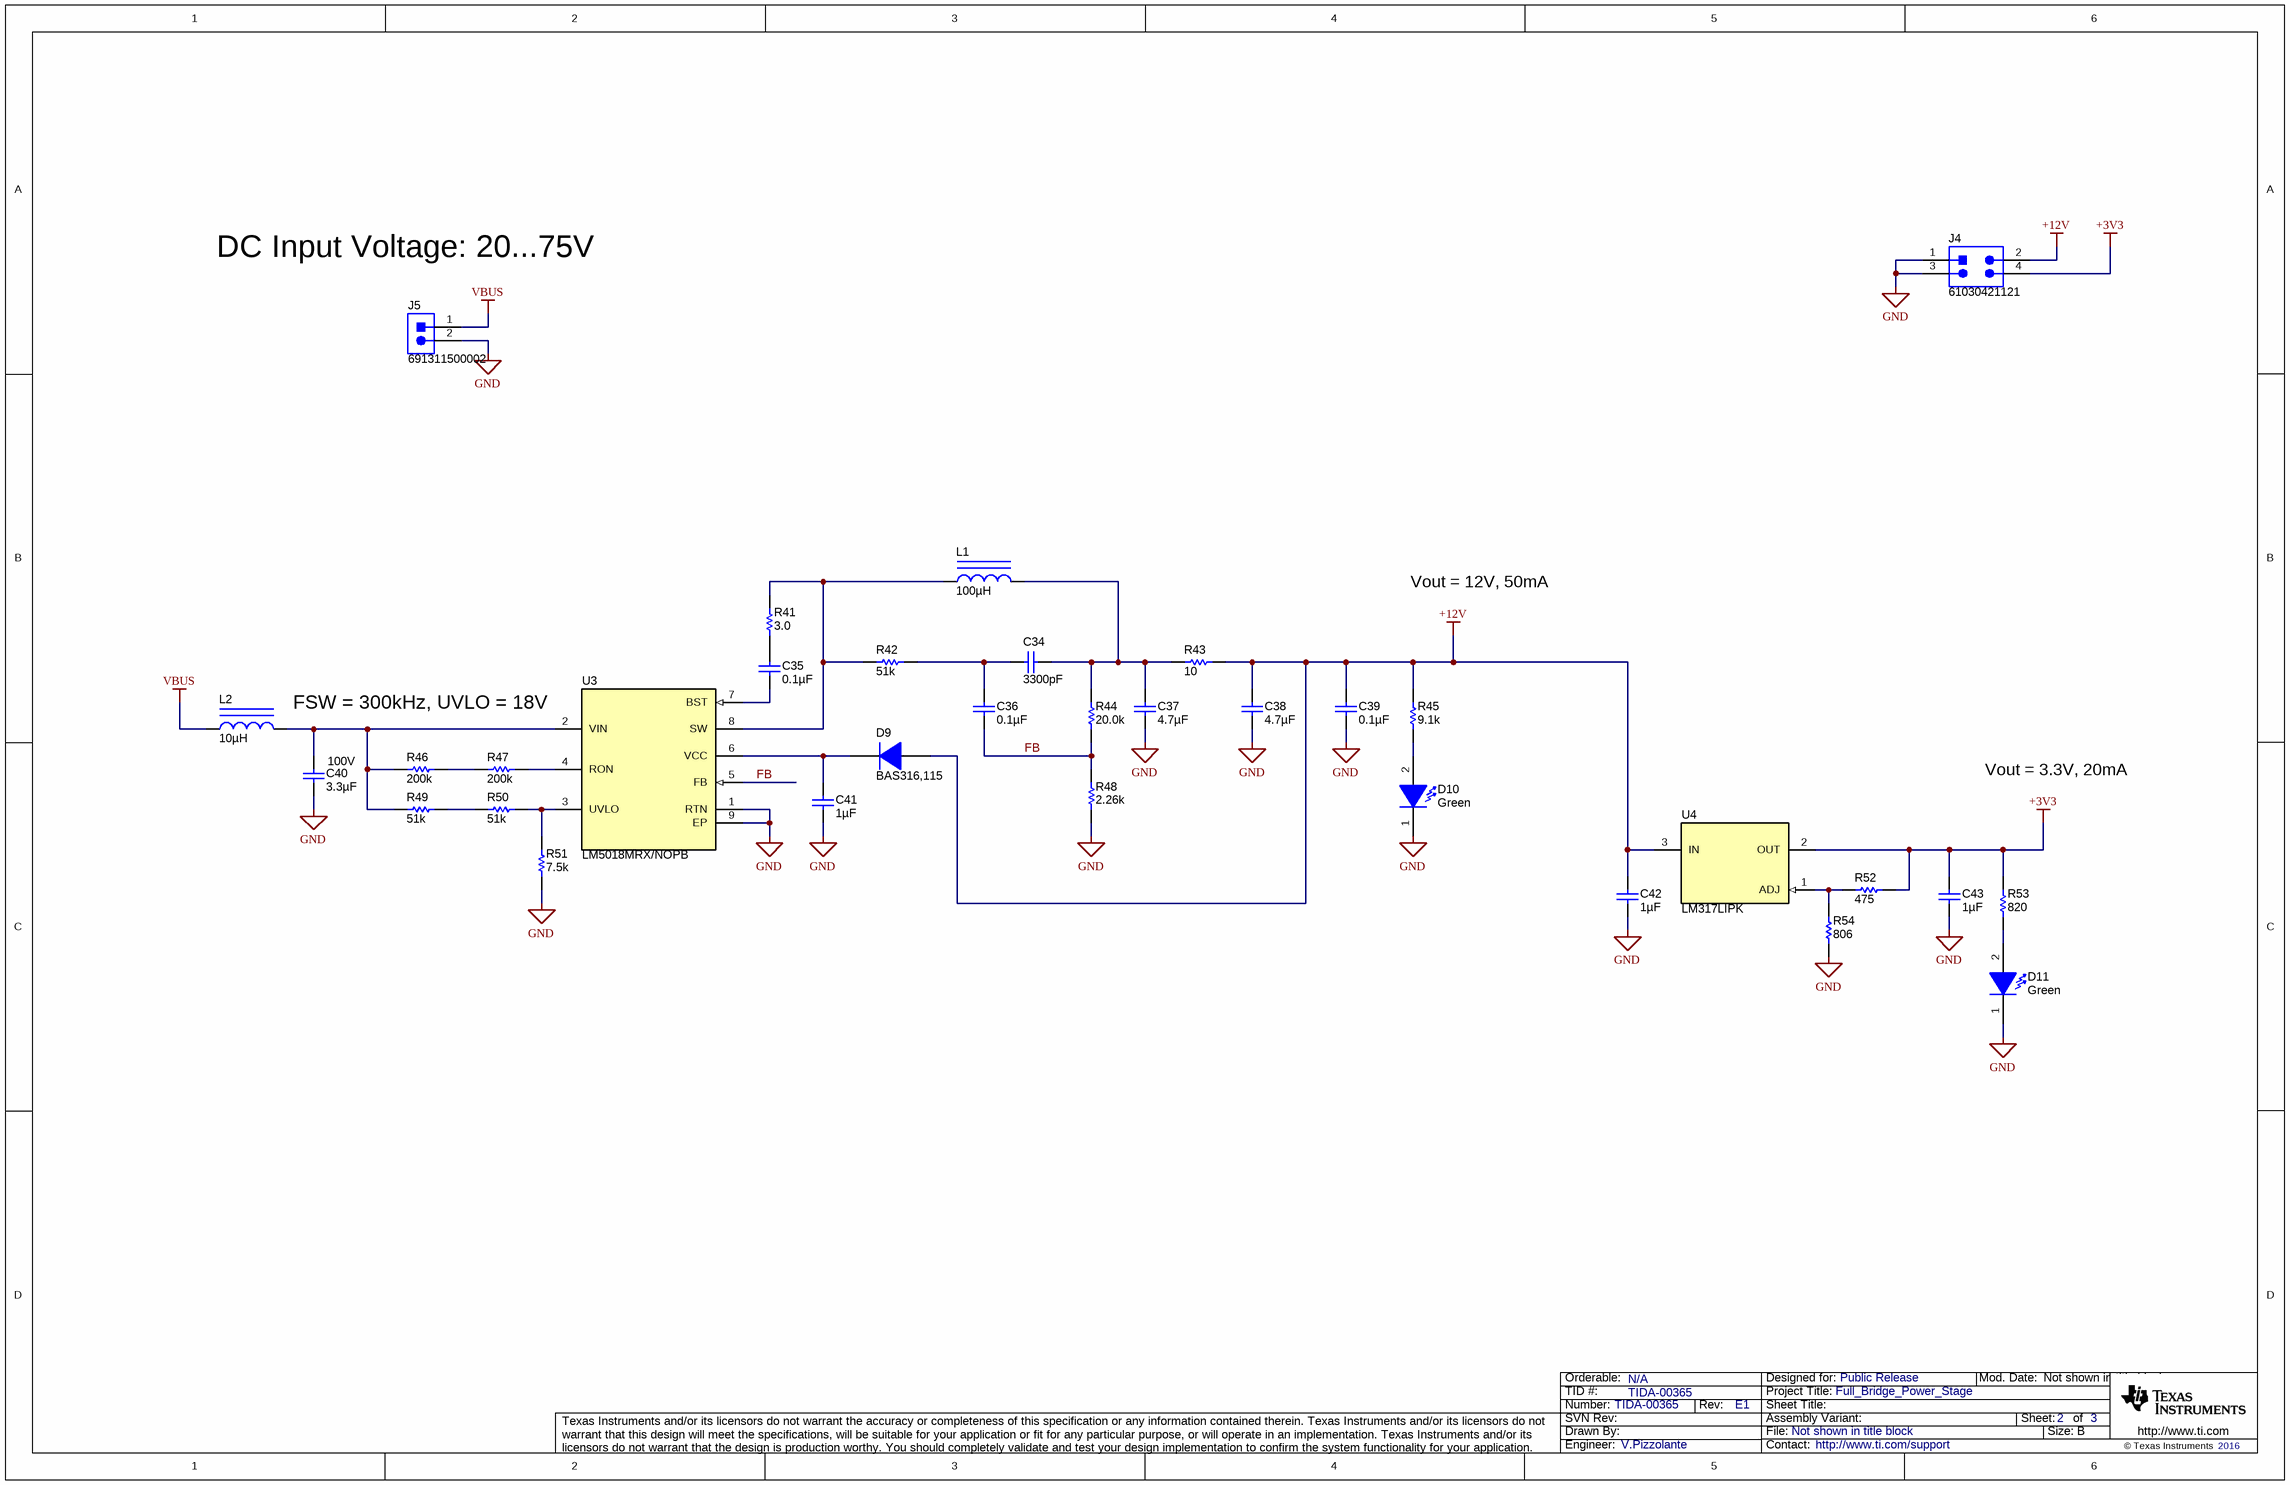
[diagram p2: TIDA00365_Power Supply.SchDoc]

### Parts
C34  ValueDisplayed: 3300pF  [0603]  (hidden comment: GRM188R72A332KA01D)
C35  ValueDisplayed: 0.1µF  [0603]  (hidden comment: GRM188R72A104KA35D)
C36  ValueDisplayed: 0.1µF  [0402]  (hidden comment: C1005X7R1E104M050BB)
C37  ValueDisplayed: 4.7µF  [0603]  (hidden comment: GRM188R61E475KE11D)
C38  ValueDisplayed: 4.7µF  [0603]  (hidden comment: GRM188R61E475KE11D)
C39  ValueDisplayed: 0.1µF  [0402]  (hidden comment: C1005X7R1E104M050BB)
C40  ValueDisplayed: 3.3µF  Value2: 100V  [1206_190]  (hidden comment: C3216X7S2A335M160AB)
C41  ValueDisplayed: 1µF  [0603]  (hidden comment: C1608X5R1C105K)
C42  ValueDisplayed: 1µF  [0603]  (hidden comment: C1608X5R1C105K)
C43  ValueDisplayed: 1µF  [0603]  (hidden comment: C1608X5R1C105K)
D9  BAS316,115  [sod-323]
D10  value Green  [WL-SMCW_GREEN]  (hidden comment: 150060GS75000)
D11  value Green  [WL-SMCW_GREEN]  (hidden comment: 150060GS75000)
J4  61030421121  [Wurth_61030421121]
J5  691311500002  [Wurth_691311500002]
L1  ValueDisplayed: 100µH  [WE-LQS_4012]  (hidden comment: 74404041101)
L2  ValueDisplayed: 10µH  [WE-PMI_1008]  (hidden comment: 74479887310)
R41  ValueDisplayed: 3.0  [0402]  (hidden comment: CRCW04023R00JNED)
R42  ValueDisplayed: 51k  [0402]  (hidden comment: CRCW040251K0JNED)
R43  ValueDisplayed: 10  [0603]  (hidden comment: CRCW060310R0JNEA)
R44  ValueDisplayed: 20.0k  [0402]  (hidden comment: CRCW040220K0FKED)
R45  ValueDisplayed: 9.1k  [0402]  (hidden comment: CRCW04029K10JNED)
R46  ValueDisplayed: 200k  [0402]  (hidden comment: CRCW0402200KJNED)
R47  ValueDisplayed: 200k  [0402]  (hidden comment: CRCW0402200KJNED)
R48  ValueDisplayed: 2.26k  [0402]  (hidden comment: CRCW04022K26FKED)
R49  ValueDisplayed: 51k  [0402]  (hidden comment: CRCW040251K0JNED)
R50  ValueDisplayed: 51k  [0402]  (hidden comment: CRCW040251K0JNED)
R51  ValueDisplayed: 7.5k  [0402]  (hidden comment: CRCW04027K50JNED)
R52  ValueDisplayed: 475  [0402]  (hidden comment: CRCW0402475RFKED)
R53  ValueDisplayed: 820  [0402]  (hidden comment: CRCW0402820RJNED)
R54  ValueDisplayed: 806  [0402]  (hidden comment: CRCW0402806RFKED)
U3  LM5018MRX/NOPB  [DDA0008B_N]
U4  LM317LIPK  [PK0003A_N]

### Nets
+3V3: C43.1 J4.4 R52.2 R53.2 U4.2(OUT)
+12V: C38.1 C39.1 C42.1 D9.2(A) J4.2 R43.2 R45.2 U4.3(IN)
GND: C37.2 C38.2 C39.2 C40.2 C41.2 C42.2 C43.2 D10.1(K) D11.1(K) J4.1 J4.3 J5.2 R48.1 R51.1 R54.1 U3.1(RTN) U3.9(EP)
VBUS: J5.1 L2.1
FB: C36.2 R44.1 R48.2 U3.5(FB)
NetC34_1: C34.1 C37.1 L1.2 R43.1 R44.2
NetC34_2: C34.2 C36.1 R42.2
NetC35_1: C35.1 U3.7(BST)
NetC35_2: C35.2 R41.1
NetC40_1: C40.1 L2.2 R46.1 R49.1 U3.2(VIN)
NetC41_1: C41.1 D9.1(K) U3.6(VCC)
NetD10_2: D10.2(A) R45.1
NetD11_2: D11.2(A) R53.1
NetL1_1: L1.1 R41.2 R42.1 U3.8(SW)
NetR46_2: R46.2 R47.1
NetR47_2: R47.2 U3.4(RON)
NetR49_2: R49.2 R50.1
NetR50_2: R50.2 R51.2 U3.3(UVLO)
NetR52_1: R52.1 R54.2 U4.1(ADJ)

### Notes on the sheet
- DC Input Voltage: 20...75V
- Vout = 12V, 50mA
- FSW = 300kHz, UVLO = 18V
- Vout = 3.3V, 20mA

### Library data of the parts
C34 = GRM188R72A332KA01D: CAP, CERM, 3300 pF, 100 V, +/- 10%, X7R, 0603; Manufacturer: MuRata; Polarized: N; CompType: Capacitor; Value: 3300pF; U/M: EA; Cap_F: 0.0000000033; Tolerance_%: 10; Value1: Unknown; VDC_V: 100; Value2: 100V; TaMin_C: -55; TaMax_C: 125; AEC Category: Q200
C35 = GRM188R72A104KA35D: CAP, CERM, 0.1 µF, 100 V, +/- 10%, X7R, 0603; Manufacturer: MuRata; Polarized: N; CompType: Capacitor; Value: 0.1uF; U/M: EA; Cap_F: 0.0000001; Tolerance_%: 10; Value1: Unknown; VDC_V: 100; Value2: 100V; TaMin_C: -55; TaMax_C: 125; AEC Category: Q200
C36 C39 = C1005X7R1E104M050BB: as C18 on sheet TIDA00365_Full Bridge
C37 C38 = GRM188R61E475KE11D: CAP, CERM, 4.7 µF, 25 V, +/- 10%, X5R, 0603; Manufacturer: MuRata; Polarized: N; CompType: Capacitor; Value: 4.7uF; U/M: EA; Cap_F: 0.0000047; Tolerance_%: 10; Value1: Unknown; VDC_V: 25; Value2: 25V; TaMin_C: -55; TaMax_C: 85; AEC Category: Q200
C40 = C3216X7S2A335M160AB: as C3 on sheet TIDA00365_Full Bridge
C41-C43 = C1608X5R1C105K: CAP, CERM, 1 µF, 16 V, +/- 10%, X5R, 0603; Manufacturer: TDK; Polarized: N; CompType: Capacitor; Value: 1uF; U/M: EA; Cap_F: 0.000001; Tolerance_%: 10; ESR_ohm: 0.0057; Value1: 0.0057 ohm; VDC_V: 16; Value2: 16V; TaMin_C: -55; TaMax_C: 85; AEC Category: Q200
D9 = BAS316,115: as D1 on sheet TIDA00365_Full Bridge
D10 D11 = 150060GS75000: LED, Green, SMD; Manufacturer: Wurth Elektronik; Type: InGaN; Vf_V: 3.2; Value2: 3.2V; Io_A: 0.02; Tjmax_C: 85; Value1: W; Angle: 140; U/M: EA
J4 = 61030421121: as J1 on sheet TIDA00365_Interfaces
J5 = 691311500002: Header (Shrouded), 5.08mm, 2x1, Tin, TH; Manufacturer: Wurth Elektronik; SymbolCreator: a0412235; Pitch_mm: 5.08; Gender: Male; Shrouded: Y; Row_Count: 1; Current_A: 20; Voltage_V: 300
L1 = 74404041101: Inductor, Wirewound, Ferrite, 100 µH, 0.35 A, 1.697 ohm, SMD; Manufacturer: Wurth Elektronik; Value: 100uH; Ind_H: 100.0E-6; Imax_A: 0.35; Irms: 0.43A @ 40C rise; Isat: 0.35A @ 30% inductance drop; DCR_ohm: 1.697; Value2: 0.35A; AEC Category: Q200; AEC Qualified: N
L2 = 74479887310: Inductor, Shielded Drum Core, Metal Composite, 10 µH, 0.35 A, 0.7 ohm, SMD; Manufacturer: Wurth Elektronik; Value: 10uH; Ind_H: 10.0E-6; Imax_A: 0.35; Irms: 0.5A @ 40C rise; Isat: 0.35A @ 30% inductance drop; DCR_ohm: 0.7; Value1: 0.7 ohm; Value2: 0.35A; AEC Category: Q200
R41 = CRCW04023R00JNED: RES, 3.0, 5%, 0.063 W, 0402; Manufacturer: Vishay-Dale; CompType: Resistor; Value: 3.0; Res_ohm: 3; Value_Code: 3R00; Tolerance_%: 5; Power_W: 0.063; Value2: 0.063W; VDC_V: 50; TempCo: 200 ppm/C; EIA_Code: E24; U/M: EA; AEC Category: Q200
R42 R49 R50 = CRCW040251K0JNED: RES, 51 k, 5%, 0.063 W, 0402; Manufacturer: Vishay-Dale; CompType: Resistor; Value: 51k; Res_ohm: 51000; Value_Code: 51k0; Tolerance_%: 5; Power_W: 0.063; Value2: 0.063W; VDC_V: 50; TempCo: 200 ppm/C; EIA_Code: E24; U/M: EA; AEC Category: Q200
R43 = CRCW060310R0JNEA: as R12 on sheet TIDA00365_Full Bridge
R44 = CRCW040220K0FKED: RES, 20.0 k, 1%, 0.063 W, 0402; Manufacturer: Vishay-Dale; CompType: Resistor; Value: 20.0k; Res_ohm: 20000; Value_Code: 20k0; Tolerance_%: 1; Power_W: 0.063; Value2: 0.063W; VDC_V: 50; TempCo: 100 ppm/C; EIA_Code: E96; U/M: EA; AEC Category: Q200
R45 = CRCW04029K10JNED: RES, 9.1 k, 5%, 0.063 W, 0402; Manufacturer: Vishay-Dale; CompType: Resistor; Value: 9.1k; Res_ohm: 9100; Value_Code: 9k10; Tolerance_%: 5; Power_W: 0.063; Value2: 0.063W; VDC_V: 50; TempCo: 200 ppm/C; EIA_Code: E24; U/M: EA; AEC Category: Q200
R46 R47 = CRCW0402200KJNED: RES, 200 k, 5%, 0.063 W, 0402; Manufacturer: Vishay-Dale; CompType: Resistor; Value: 200k; Res_ohm: 200000; Tolerance_%: 5; Power_W: 0.063; Value2: 0.063W; VDC_V: 50; TempCo: 200 ppm/C; EIA_Code: E24; U/M: EA; AEC Category: Q200
R48 = CRCW04022K26FKED: RES, 2.26 k, 1%, 0.063 W, 0402; Manufacturer: Vishay-Dale; CompType: Resistor; Value: 2.26k; Res_ohm: 2260; Value_Code: 2k26; Tolerance_%: 1; Power_W: 0.063; Value2: 0.063W; VDC_V: 50; TempCo: 100 ppm/C; EIA_Code: E96; U/M: EA; AEC Category: Q200
R51 = CRCW04027K50JNED: RES, 7.5 k, 5%, 0.063 W, 0402; Manufacturer: Vishay-Dale; CompType: Resistor; Value: 7.5k; Res_ohm: 7500; Value_Code: 7k50; Tolerance_%: 5; Power_W: 0.063; Value2: 0.063W; VDC_V: 50; TempCo: 200 ppm/C; EIA_Code: E24; U/M: EA; AEC Category: Q200
R52 = CRCW0402475RFKED: RES, 475, 1%, 0.063 W, 0402; Manufacturer: Vishay-Dale; CompType: Resistor; Value: 475; Value_Code: 475R; Tolerance_%: 1; Power_W: 0.063; Value2: 0.063W; VDC_V: 50; TempCo: 100 ppm/C; EIA_Code: E96; U/M: EA; AEC Category: Q200
R53 = CRCW0402820RJNED: RES, 820, 5%, 0.063 W, 0402; Manufacturer: Vishay-Dale; CompType: Resistor; Value: 820; Value_Code: 820R; Tolerance_%: 5; Power_W: 0.063; Value2: 0.063W; VDC_V: 50; TempCo: 200 ppm/C; EIA_Code: E24; U/M: EA; AEC Category: Q200
R54 = CRCW0402806RFKED: RES, 806, 1%, 0.063 W, 0402; Manufacturer: Vishay-Dale; CompType: Resistor; Value: 806; Value_Code: 806R; Tolerance_%: 1; Power_W: 0.063; Value2: 0.063W; VDC_V: 50; TempCo: 100 ppm/C; EIA_Code: E96; U/M: EA; AEC Category: Q200
U3 = LM5018MRX/NOPB: 100V, 300mA Constant On-Time Synchronous Buck Regulator, DDA0008B; Alternate PartNumber: LM5018MR/NOPB; Manufacturer: Texas Instruments; SymbolCreator: a0412235; CompType: IC; U/M: EA
U4 = LM317LIPK: 3-Terminal Adjustable Regulator, PK0003A; Manufacturer: Texas Instruments; SymbolCreater: a0411947; CompType: IC; U/M: EA

## Sheet TIDA00365_Protections.SchDoc
size 431 x 279 mm; Date: Not shown in title block; ApprovedBy: Not shown in title block; CheckedBy: Not shown in title block; Author: Not shown in title block; CompanyName: Not shown in title block; Engineer: Not shown in title block; Organization: Not shown in title block; Address1: Not shown in title block; Address2: Not shown in title block; Address3: Not shown in title block; Address4: Not shown in title block; DocumentNumber: 1; Revision: Use project parameter SCH_Rev; SheetNumber: 2; SheetTotal: 3
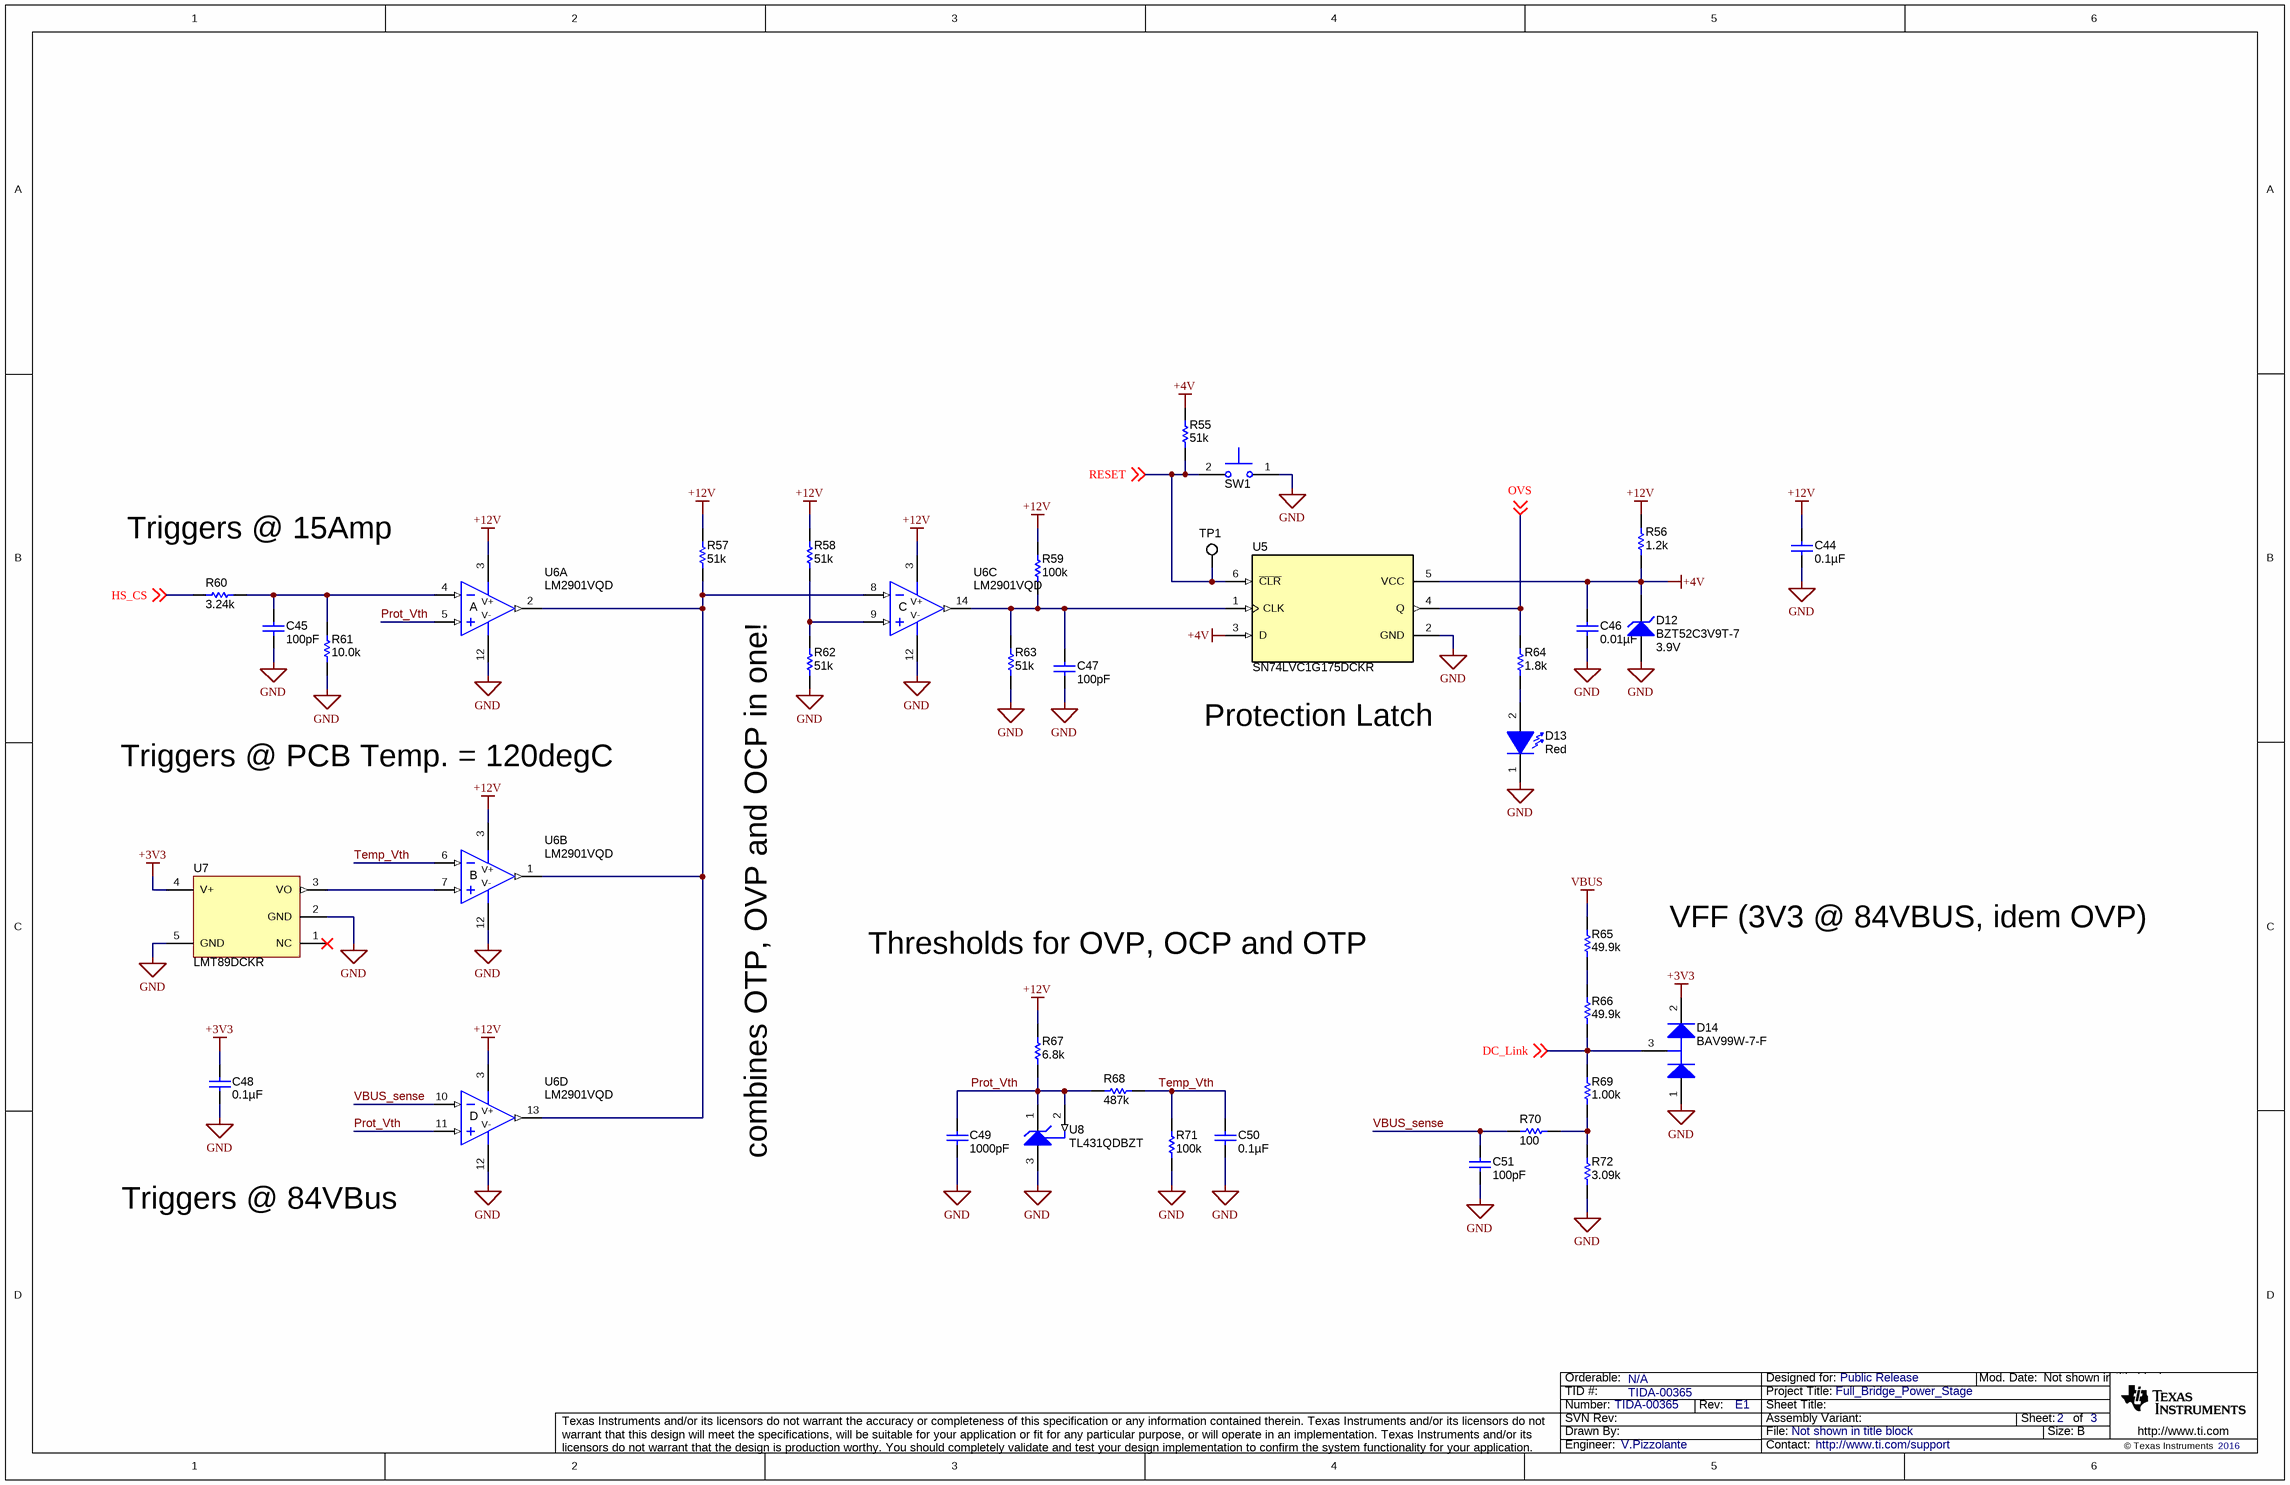
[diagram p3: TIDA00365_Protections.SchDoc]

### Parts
C44  ValueDisplayed: 0.1µF  [0402]  (hidden comment: C1005X7R1E104M050BB)
C45  ValueDisplayed: 100pF  [0402]  (hidden comment: CC0402KRX7R9BB101)
C46  ValueDisplayed: 0.01µF  [0402]  (hidden comment: 885012205031)
C47  ValueDisplayed: 100pF  [0402]  (hidden comment: CC0402KRX7R9BB101)
C48  ValueDisplayed: 0.1µF  [0402]  (hidden comment: C1005X7R1E104M050BB)
C49  ValueDisplayed: 1000pF  [0402]  (hidden comment: 885012205044)
C50  ValueDisplayed: 0.1µF  [0402]  (hidden comment: 885012105016)
C51  ValueDisplayed: 100pF  [0402]  (hidden comment: CC0402KRX7R9BB101)
D12  BZT52C3V9T-7  value 3.9V  [SOD-523]
D13  value Red  [WL-SMCW_RED]  (hidden comment: 150060RS75000)
D14  BAV99W-7-F  [SOT-323]
R55  ValueDisplayed: 51k  [0402]  (hidden comment: CRCW040251K0JNED)
R56  ValueDisplayed: 1.2k  [0402]  (hidden comment: CRCW04021K20JNED)
R57  ValueDisplayed: 51k  [0402]  (hidden comment: CRCW040251K0JNED)
R58  ValueDisplayed: 51k  [0402]  (hidden comment: CRCW040251K0JNED)
R59  ValueDisplayed: 100k  [0402]  (hidden comment: CRCW0402100KJNED)
R60  ValueDisplayed: 3.24k  [0402]  (hidden comment: CRCW04023K24FKED)
R61  ValueDisplayed: 10.0k  [0402]  (hidden comment: CRCW040210K0FKED)
R62  ValueDisplayed: 51k  [0402]  (hidden comment: CRCW040251K0JNED)
R63  ValueDisplayed: 51k  [0402]  (hidden comment: CRCW040251K0JNED)
R64  ValueDisplayed: 1.8k  [0402]  (hidden comment: CRCW04021K80JNED)
R65  ValueDisplayed: 49.9k  [0402]  (hidden comment: CRCW040249K9FKED)
R66  ValueDisplayed: 49.9k  [0402]  (hidden comment: CRCW040249K9FKED)
R67  ValueDisplayed: 6.8k  [0402]  (hidden comment: CRCW04026K80JNED)
R68  ValueDisplayed: 487k  [0402]  (hidden comment: CRCW0402487KFKED)
R69  ValueDisplayed: 1.00k  [0402]  (hidden comment: CRCW04021K00FKED)
R70  ValueDisplayed: 100  [0402]  (hidden comment: CRCW0402100RJNED)
R71  ValueDisplayed: 100k  [0402]  (hidden comment: CRCW0402100KFKED)
R72  ValueDisplayed: 3.09k  [0402]  (hidden comment: CRCW04023K09FKED)
SW1  TL1015AF160QG  [SW_TL1015AF160QG]  (value not drawn)
TP1  5002  [Keystone5002]  (value not drawn)
U5  SN74LVC1G175DCKR  [DCK0006A_N]
U6  LM2901VQD  [D0014A_N]  (parts A,B,C,D of 4)
U7  LMT89DCKR  [DCK0005A_N]
U8  TL431QDBZT  [DBZ0003A_N]

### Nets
+3V3: C48.1 D14.2(K) U7.4(V+)
+4V: C46.1 D12.1(K) R55.2 R56.1 U5.3(D) U5.5(VCC)
+12V: C44.1 R56.2 R57.1 R58.1 R59.2 R67.2 U6.3(V+)
GND: C44.2 C45.2 C46.2 C47.2 C48.2 C49.2 C50.2 C51.2 D12.2(A) D13.1(K) D14.1(A) R61.1 R62.2 R63.1 R71.1 R72.1 SW1.1 U5.2(GND) U6.12(V-) U7.2(GND) U7.5(GND) U8.3(ANODE)
VBUS: R65.2
DC_Link: D14.3(C) R66.1 R69.2 ; off-sheet DC_Link
HS_CS: R60.1 ; off-sheet HS_CS  [project net BOUT]
OVS: R64.1 U5.4(Q) ; off-sheet OVS
Prot_Vth: C49.1 R67.1 R68.2 U6.5(+IN1) U6.11(+IN4) U8.1(CATHODE) U8.2(REF)
RESET: R55.1 SW1.2 TP1.1 U5.6(~{CLR}) ; off-sheet RESET
Temp_Vth: C50.1 R68.1 R71.2 U6.6(-IN2)
VBUS_sense: C51.1 R70.1 U6.10(-IN4)
NetC45_1: C45.1 R60.2 R61.2 U6.4(-IN1)
NetC47_1: C47.1 R59.1 R63.2 U5.1(CLK) U6.14(OUT3)
NetD13_2: D13.2(A) R64.2
NetR57_2: R57.2 U6.1(OUT2) U6.2(OUT1) U6.8(-IN3) U6.13(OUT4)
NetR58_2: R58.2 R62.1 U6.9(+IN3)
NetR65_1: R65.1 R66.2
NetR69_1: R69.1 R70.2 R72.2
NetU6_7: U6.7(+IN2) U7.3(VO)

Not connected (* = marked no-connect by the designer): U7 1(NC)*

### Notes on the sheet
- Triggers @ 15Amp
- Triggers @ PCB Temp. = 120degC
- Protection Latch
- (near R62) combines OTP, OVP and OCP in one!
- Thresholds for OVP, OCP and OTP
- VFF (3V3 @ 84VBUS, idem OVP)
- Triggers @ 84VBus

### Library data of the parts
C44 C48 = C1005X7R1E104M050BB: as C18 on sheet TIDA00365_Full Bridge
C45 C47 C51 = CC0402KRX7R9BB101: as C26 on sheet TIDA00365_Interfaces
C46 = 885012205031: as C16 on sheet TIDA00365_Full Bridge
C49 = 885012205044: CAP, CERM, 1000 pF, 25 V, +/- 10%, X7R, 0402; Manufacturer: Wurth Elektronik; Polarized: N; CompType: Capacitor; Value: 1000pF; U/M: EA; Cap_F: 0.000000001; Tolerance_%: 10; Value1: Unknown; VDC_V: 25; Value2: 25V; TaMin_C: -55; TaMax_C: 125; AEC Category: Q200
C50 = 885012105016: CAP, CERM, 0.1 µF, 16 V, +/- 20%, X5R, 0402; Manufacturer: Wurth Elektronik; Polarized: N; CompType: Capacitor; Value: 0.1uF; U/M: EA; Cap_F: 0.0000001; Tolerance_%: 20; Value1: Unknown; VDC_V: 16; Value2: 16V; TaMin_C: -55; TaMax_C: 85; AEC Category: Q200
D12 = BZT52C3V9T-7: Diode, Zener, 3.9 V, 300 mW, SOD-523; Manufacturer: Diodes Inc.; SymbolCreator: a0412235; U/M: EA; Power_W: 0.3; Vz_V: 3.9; Value1: 0.3W; RJA_CperW: 417; AEC Category: Q101
D13 = 150060RS75000: as D7 on sheet TIDA00365_Interfaces
D14 = BAV99W-7-F: Diode, Switching, 75 V, 0.15 A, SOT-323; Manufacturer: Diodes Inc.; U/M: EA; Vf_V: 1.25; Value: 75V; Value1: 0.15A; Value2: 1.25V; Io_A: 0.15; Vr_V: 75; TJmax_C: 150; AEC Category: Q101
R55 R57 R58 R62 R63 = CRCW040251K0JNED: as R42 on sheet TIDA00365_Power Supply
R56 = CRCW04021K20JNED: as R39 on sheet TIDA00365_Interfaces
R59 = CRCW0402100KJNED: RES, 100 k, 5%, 0.063 W, 0402; Manufacturer: Vishay-Dale; CompType: Resistor; Value: 100k; Res_ohm: 100000; Tolerance_%: 5; Power_W: 0.063; Value2: 0.063W; VDC_V: 50; TempCo: 200 ppm/C; EIA_Code: E24; U/M: EA; AEC Category: Q200
R60 = CRCW04023K24FKED: RES, 3.24 k, 1%, 0.063 W, 0402; Manufacturer: Vishay-Dale; CompType: Resistor; Value: 3.24k; Res_ohm: 3240; Value_Code: 3k24; Tolerance_%: 1; Power_W: 0.063; Value2: 0.063W; VDC_V: 50; TempCo: 100 ppm/C; EIA_Code: E96; U/M: EA; AEC Category: Q200
R61 = CRCW040210K0FKED: RES, 10.0 k, 1%, 0.063 W, 0402; Manufacturer: Vishay-Dale; CompType: Resistor; Value: 10.0k; Res_ohm: 10000; Value_Code: 10k0; Tolerance_%: 1; Power_W: 0.063; Value2: 0.063W; VDC_V: 50; TempCo: 100 ppm/C; EIA_Code: E96; U/M: EA; AEC Category: Q200
R64 = CRCW04021K80JNED: RES, 1.8 k, 5%, 0.063 W, 0402; Manufacturer: Vishay-Dale; CompType: Resistor; Value: 1.8k; Res_ohm: 1800; Value_Code: 1k80; Tolerance_%: 5; Power_W: 0.063; Value2: 0.063W; VDC_V: 50; TempCo: 200 ppm/C; EIA_Code: E24; U/M: EA; AEC Category: Q200
R65 R66 = CRCW040249K9FKED: as R25 on sheet TIDA00365_Interfaces
R67 = CRCW04026K80JNED: RES, 6.8 k, 5%, 0.063 W, 0402; Manufacturer: Vishay-Dale; CompType: Resistor; Value: 6.8k; Res_ohm: 6800; Value_Code: 6k80; Tolerance_%: 5; Power_W: 0.063; Value2: 0.063W; VDC_V: 50; TempCo: 200 ppm/C; EIA_Code: E24; U/M: EA; AEC Category: Q200
R68 = CRCW0402487KFKED: RES, 487 k, 1%, 0.063 W, 0402; Manufacturer: Vishay-Dale; CompType: Resistor; Value: 487k; Res_ohm: 487000; Tolerance_%: 1; Power_W: 0.063; Value2: 0.063W; VDC_V: 50; TempCo: 100 ppm/C; EIA_Code: E96; U/M: EA; AEC Category: Q200
R69 = CRCW04021K00FKED: RES, 1.00 k, 1%, 0.063 W, 0402; Manufacturer: Vishay-Dale; CompType: Resistor; Value: 1.00k; Res_ohm: 1000; Value_Code: 1k00; Tolerance_%: 1; Power_W: 0.063; Value2: 0.063W; VDC_V: 50; TempCo: 100 ppm/C; EIA_Code: E96; U/M: EA; AEC Category: Q200
R70 = CRCW0402100RJNED: RES, 100, 5%, 0.063 W, 0402; Manufacturer: Vishay-Dale; CompType: Resistor; Value: 100; Value_Code: 100R; Tolerance_%: 5; Power_W: 0.063; Value2: 0.063W; VDC_V: 50; TempCo: 200 ppm/C; EIA_Code: E24; U/M: EA; AEC Category: Q200
R71 = CRCW0402100KFKED: RES, 100 k, 1%, 0.063 W, 0402; Manufacturer: Vishay-Dale; CompType: Resistor; Value: 100k; Res_ohm: 100000; Tolerance_%: 1; Power_W: 0.063; Value2: 0.063W; VDC_V: 50; TempCo: 100 ppm/C; EIA_Code: E96; U/M: EA; AEC Category: Q200
R72 = CRCW04023K09FKED: RES, 3.09 k, 1%, 0.063 W, 0402; Manufacturer: Vishay-Dale; CompType: Resistor; Value: 3.09k; Res_ohm: 3090; Value_Code: 3k09; Tolerance_%: 1; Power_W: 0.063; Value2: 0.063W; VDC_V: 50; TempCo: 100 ppm/C; EIA_Code: E96; U/M: EA; AEC Category: Q200
SW1 = TL1015AF160QG: Switch, Tactile, SPST-NO, 0.05A, 12V, SMT; Manufacturer: E-Switch; SymbolCreator: a0412235; VDC_V: 12; SwitchFunction: Off-Mom; PositionCount: 1; CurrentRating_mA: 50
TP1 = 5002: Test Point, Miniature, White, TH; Manufacturer: Keystone; CompType: Test Point Loop; ContactFinish: Silver
U5 = SN74LVC1G175DCKR: SINGLE D-TYPE FLIP-FLOP WITH ASYNCHRONOUS CLEAR, DCK0006A; Alternate PartNumber: SN74LVC1G175DCKT; Manufacturer: Texas Instruments; SymbolCreator: Altium; CompType: IC; U/M: EA
U6 = LM2901VQD: Quad Comparator, D0014A; Manufacturer: Texas Instruments; SymbolCreator: Altium; CompType: OpAmp IC
U7 = LMT89DCKR: 2.4V, 10μA, SC70, DSBGA Temperature Sensor, DCK0005A; Alternate PartNumber: LMT89DCKT; Manufacturer: Texas Instruments; SymbolCreator: a0412235; CompType: IC; U/M: EA
U8 = TL431QDBZT: Adjustable Precision Shunt Regulator, 34 ppm / degC, 100 mA, -40 to 125 degC, 3-pin SOT-23 (DBZ), Green (RoHS & no Sb/Br); Manufacturer: Texas Instruments; Alternate PartNumber: Equivalent; Initial Accuracy @ 25/deg C(%): 2; Iout/Iz(Max)(mA): 100; Min Iz for Regulation(uA): 600; Rating: Military; SubFamily: Shunt Voltage Reference; Temp Coeff(Max)(ppm/ degree C): 92; Temp Coeff(Typ)(ppm/ degree C): 34; VO Adj(Max)(V): 36; VO Adj(Min)(V): 2.495

## Sheet TIDA00365_Hardware.SchDoc
size 431 x 279 mm; Date: Not shown in title block; ApprovedBy: Not shown in title block; CheckedBy: Not shown in title block; Author: Not shown in title block; CompanyName: Not shown in title block; Engineer: Not shown in title block; Organization: Not shown in title block; Address1: Not shown in title block; Address2: Not shown in title block; Address3: Not shown in title block; Address4: Not shown in title block; DocumentNumber: 1; Revision: Use project parameter SCH_Rev; SheetNumber: 3; SheetTotal: 3; PageSetup: Record=PageOptions¦CenterHorizontal=True¦CenterVertical=True¦PrintScale=1.00¦XCorrection=1.00¦YCorrection=1.00¦PrintKind=0¦BorderSize=5000000¦LeftOffset=0¦BottomOffset=0¦Orientation=2¦PaperLength=1000¦PaperWidth=1000¦Scale=100¦PaperSource=15¦PrintQuality=600¦MediaType=1¦DitherType=10¦PaperKind=Letter¦PrintScaleMode=1
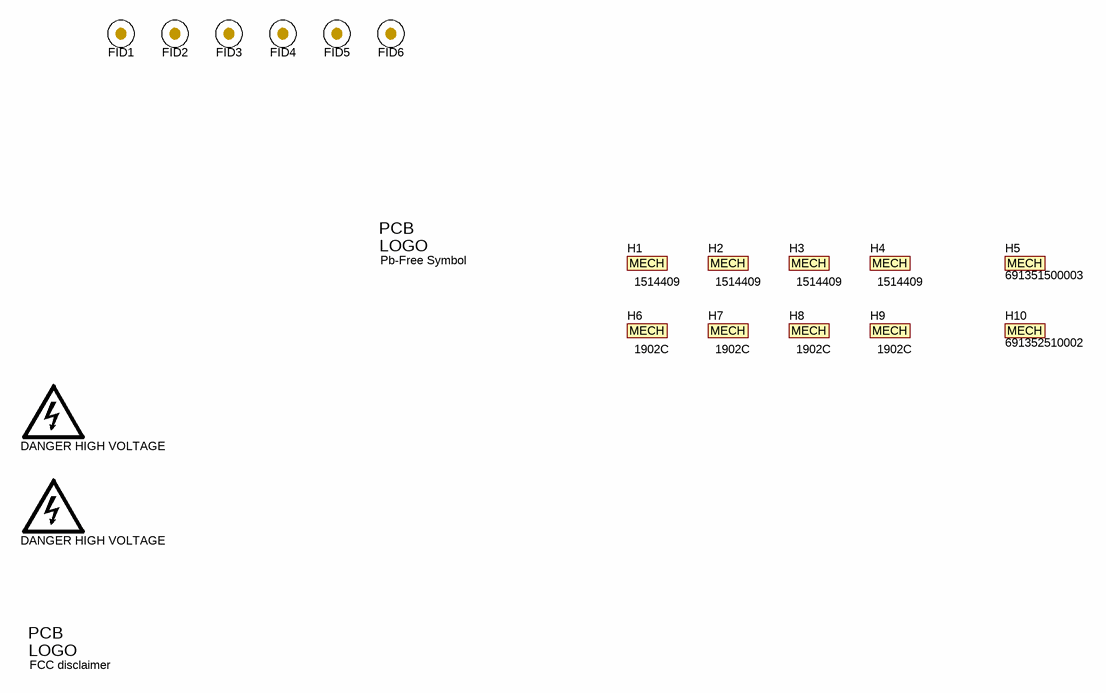
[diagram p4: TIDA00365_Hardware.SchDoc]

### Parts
DANGER_HIGH_VOLTAGE1  DANGER HIGH VOLTAGE  [IEC_HighVoltage_Small]  (no BOM)
DANGER_HIGH_VOLTAGE!1  DANGER HIGH VOLTAGE  [IEC_HighVoltage_Small]  (no BOM)
FID1  Fiducial  [Fiducial6.4-20]  (value not drawn)
FID2  Fiducial  [Fiducial6.4-20]  (value not drawn)
FID3  Fiducial  [Fiducial6.4-20]  (value not drawn)
FID4  Fiducial  [Fiducial6.4-20]  (value not drawn)
FID5  Fiducial  [Fiducial6.4-20]  (value not drawn)
FID6  Fiducial  [Fiducial6.4-20]  (value not drawn)
H1  PartNumber: 1514409  (hidden comment: 149513 - Farnell)  (mechanical)
H2  PartNumber: 1514409  (hidden comment: 149513 - Farnell)  (mechanical)
H3  PartNumber: 1514409  (hidden comment: 149513 - Farnell)  (mechanical)
H4  PartNumber: 1514409  (hidden comment: 149513 - Farnell)  (mechanical)
H5  691351500003  (mechanical)
H6  PartNumber: 1902C  (hidden comment: 149513 - Farnell)  (mechanical)
H7  PartNumber: 1902C  (hidden comment: 149513 - Farnell)  (mechanical)
H8  PartNumber: 1902C  (hidden comment: 149513 - Farnell)  (mechanical)
H9  PartNumber: 1902C  (hidden comment: 149513 - Farnell)  (mechanical)
H10  691352510002  (mechanical)
Logo1  Pb-Free Symbol  [Pb-Free_Overlay_Small]  (no BOM)
Logo2  FCC disclaimer  [FCC_disclaimer]  (no BOM)

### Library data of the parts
DANGER_HIGH_VOLTAGE1 DANGER_HIGH_VOLTAGE!1 = IEC_HighVoltage: IEC 61010-1 High Voltage Warning; SymbolCreator: a0412235
FID1-FID6 = Fiducial: Fiducial mark.  There is nothing to buy or mount.; SymbolCreator: codlsc
H1-H4 = MechPart: Will add component to BOM.  Useful for cables, nuts, etc. not in libraries; SymbolCreator: codlsc; CompType: Mechanical; U/M: EA
H5 = 691351500003: TERM BLOCK PLUG 3POS 5.08MM; Manufacturer: Wurth Elektronik; SymbolCreator: codlsc
H6-H9 = MechPart: Will add component to BOM.  Useful for cables, nuts, etc. not in libraries; Manufacturer: Standoff; SymbolCreator: codlsc; CompType: Mechanical; U/M: EA
H10 = 691352510002: TERM BLOCK PLUG 2POS 5.08MM; Manufacturer: Wurth Elektronik; SymbolCreator: codlsc
Logo1 = Pb-Free: SymbolCreator: a0412235
Logo2 = FCC_disclaimer: SymbolCreator: codlsc

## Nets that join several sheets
+3V3: TIDA00365_Full Bridge (C24.1 Q5.5 R12.2), TIDA00365_Interfaces (R39.2 R40.2), TIDA00365_Power Supply (5 pins), TIDA00365_Protections (C48.1 D14.2 U7.4)
+12V: TIDA00365_Full Bridge (C25.1 R13.2 R23.2), TIDA00365_Power Supply (8 pins), TIDA00365_Protections (7 pins)
GND: TIDA00365_Full Bridge (34 pins), TIDA00365_Interfaces (19 pins), TIDA00365_Power Supply (17 pins), TIDA00365_Protections (22 pins)
VBUS: TIDA00365_Full Bridge (10 pins), TIDA00365_Power Supply (J5.1 L2.1), TIDA00365_Protections (R65.2)
/FAULT: TIDA00365_Full Bridge (U1.15), TIDA00365_Interfaces (D8.1)
BOUT: TIDA00365_Full Bridge (U1.11), TIDA00365_Interfaces (R38.2), TIDA00365_Protections (R60.1)
DC_Link: TIDA00365_Interfaces (R37.2), TIDA00365_Protections (D14.3 R66.1 R69.2)
HS_A: TIDA00365_Full Bridge (U1.7), TIDA00365_Interfaces (C31.1 R30.2)
HS_B: TIDA00365_Full Bridge (U1.8), TIDA00365_Interfaces (C32.1 R33.2)
LS_A: TIDA00365_Full Bridge (U1.6), TIDA00365_Interfaces (C30.1 R29.2)
LS_B: TIDA00365_Full Bridge (U1.9), TIDA00365_Interfaces (C33.1 R34.2)
OVS: TIDA00365_Full Bridge (U1.16), TIDA00365_Protections (R64.1 U5.4)
PGOOD: TIDA00365_Full Bridge (U1.10), TIDA00365_Interfaces (D7.1)
phaseA: TIDA00365_Full Bridge (12 pins), TIDA00365_Interfaces (J3.3 R26.2)
phaseB: TIDA00365_Full Bridge (12 pins), TIDA00365_Interfaces (J3.1 R25.2)

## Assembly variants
001: not fitted C24 C25 Q5 R16 R23 R24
